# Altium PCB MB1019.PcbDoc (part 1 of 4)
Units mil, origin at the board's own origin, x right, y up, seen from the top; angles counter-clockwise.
Board outline 4655 x 6805 mil, 4 copper layers (TopLayer, VCC, GND, BottomLayer), stack 26.137 mil thick; 557 components, 425 nets, 1918 pads, 817 vias.
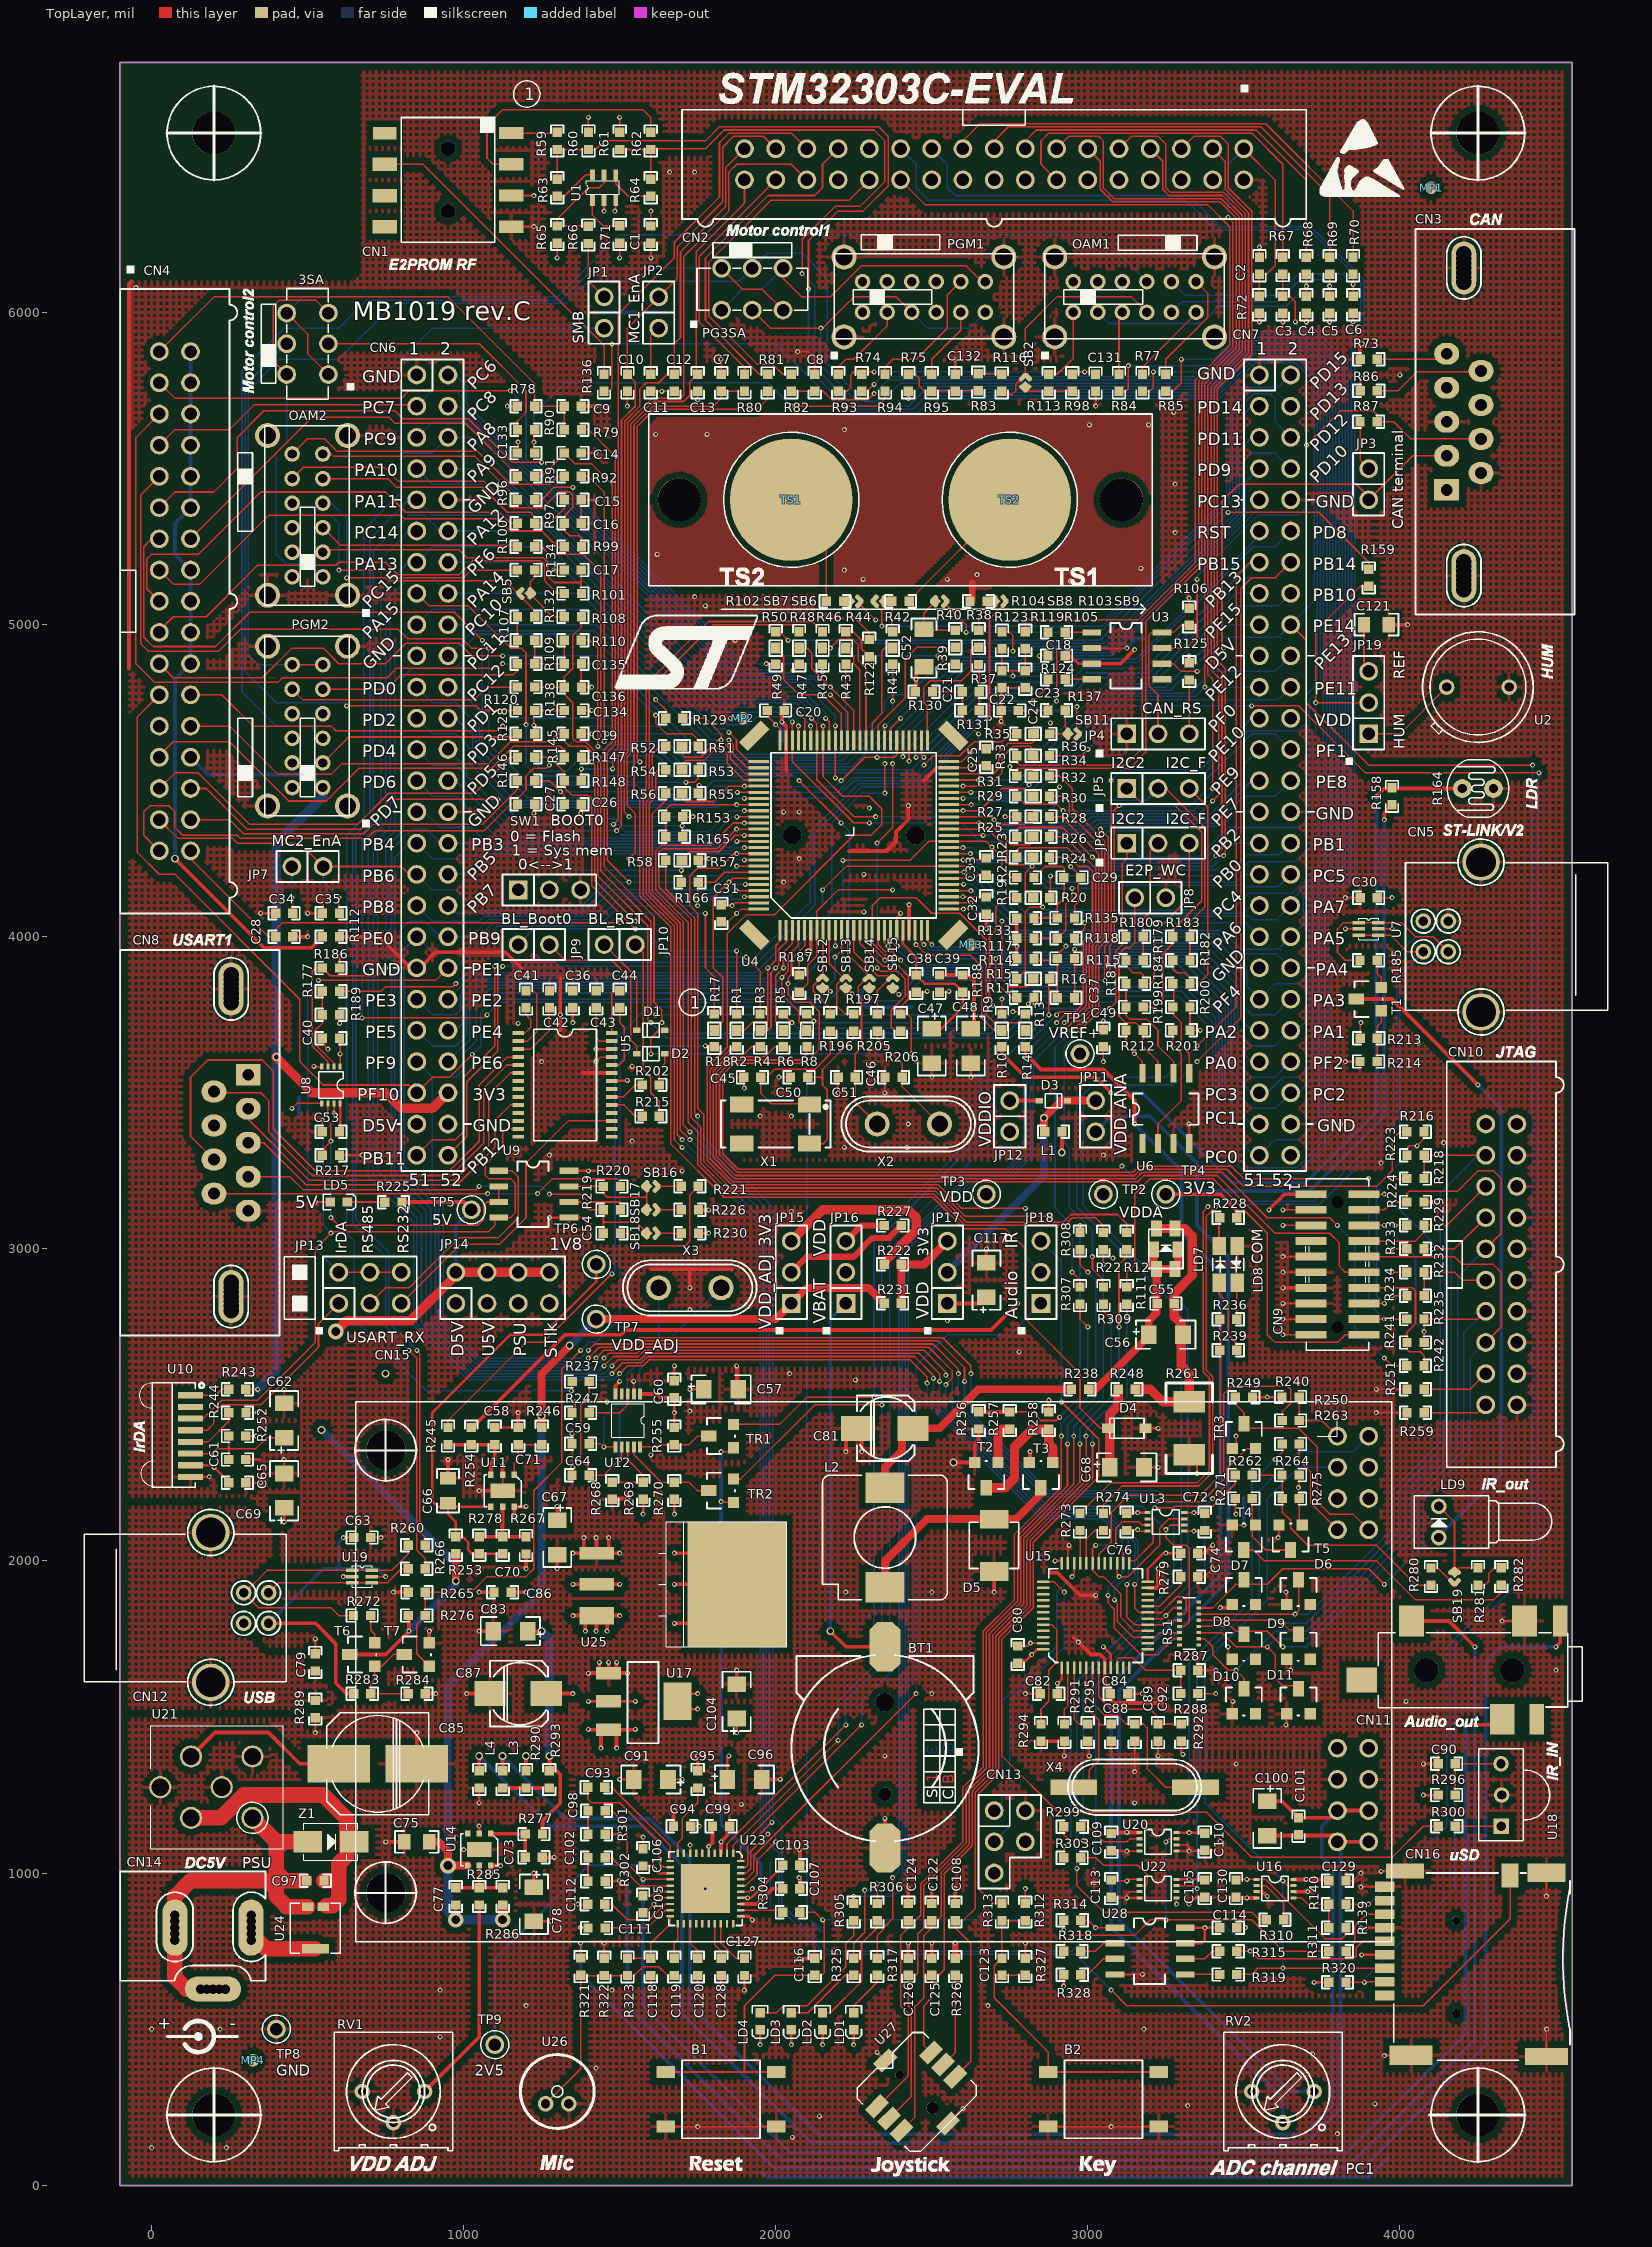
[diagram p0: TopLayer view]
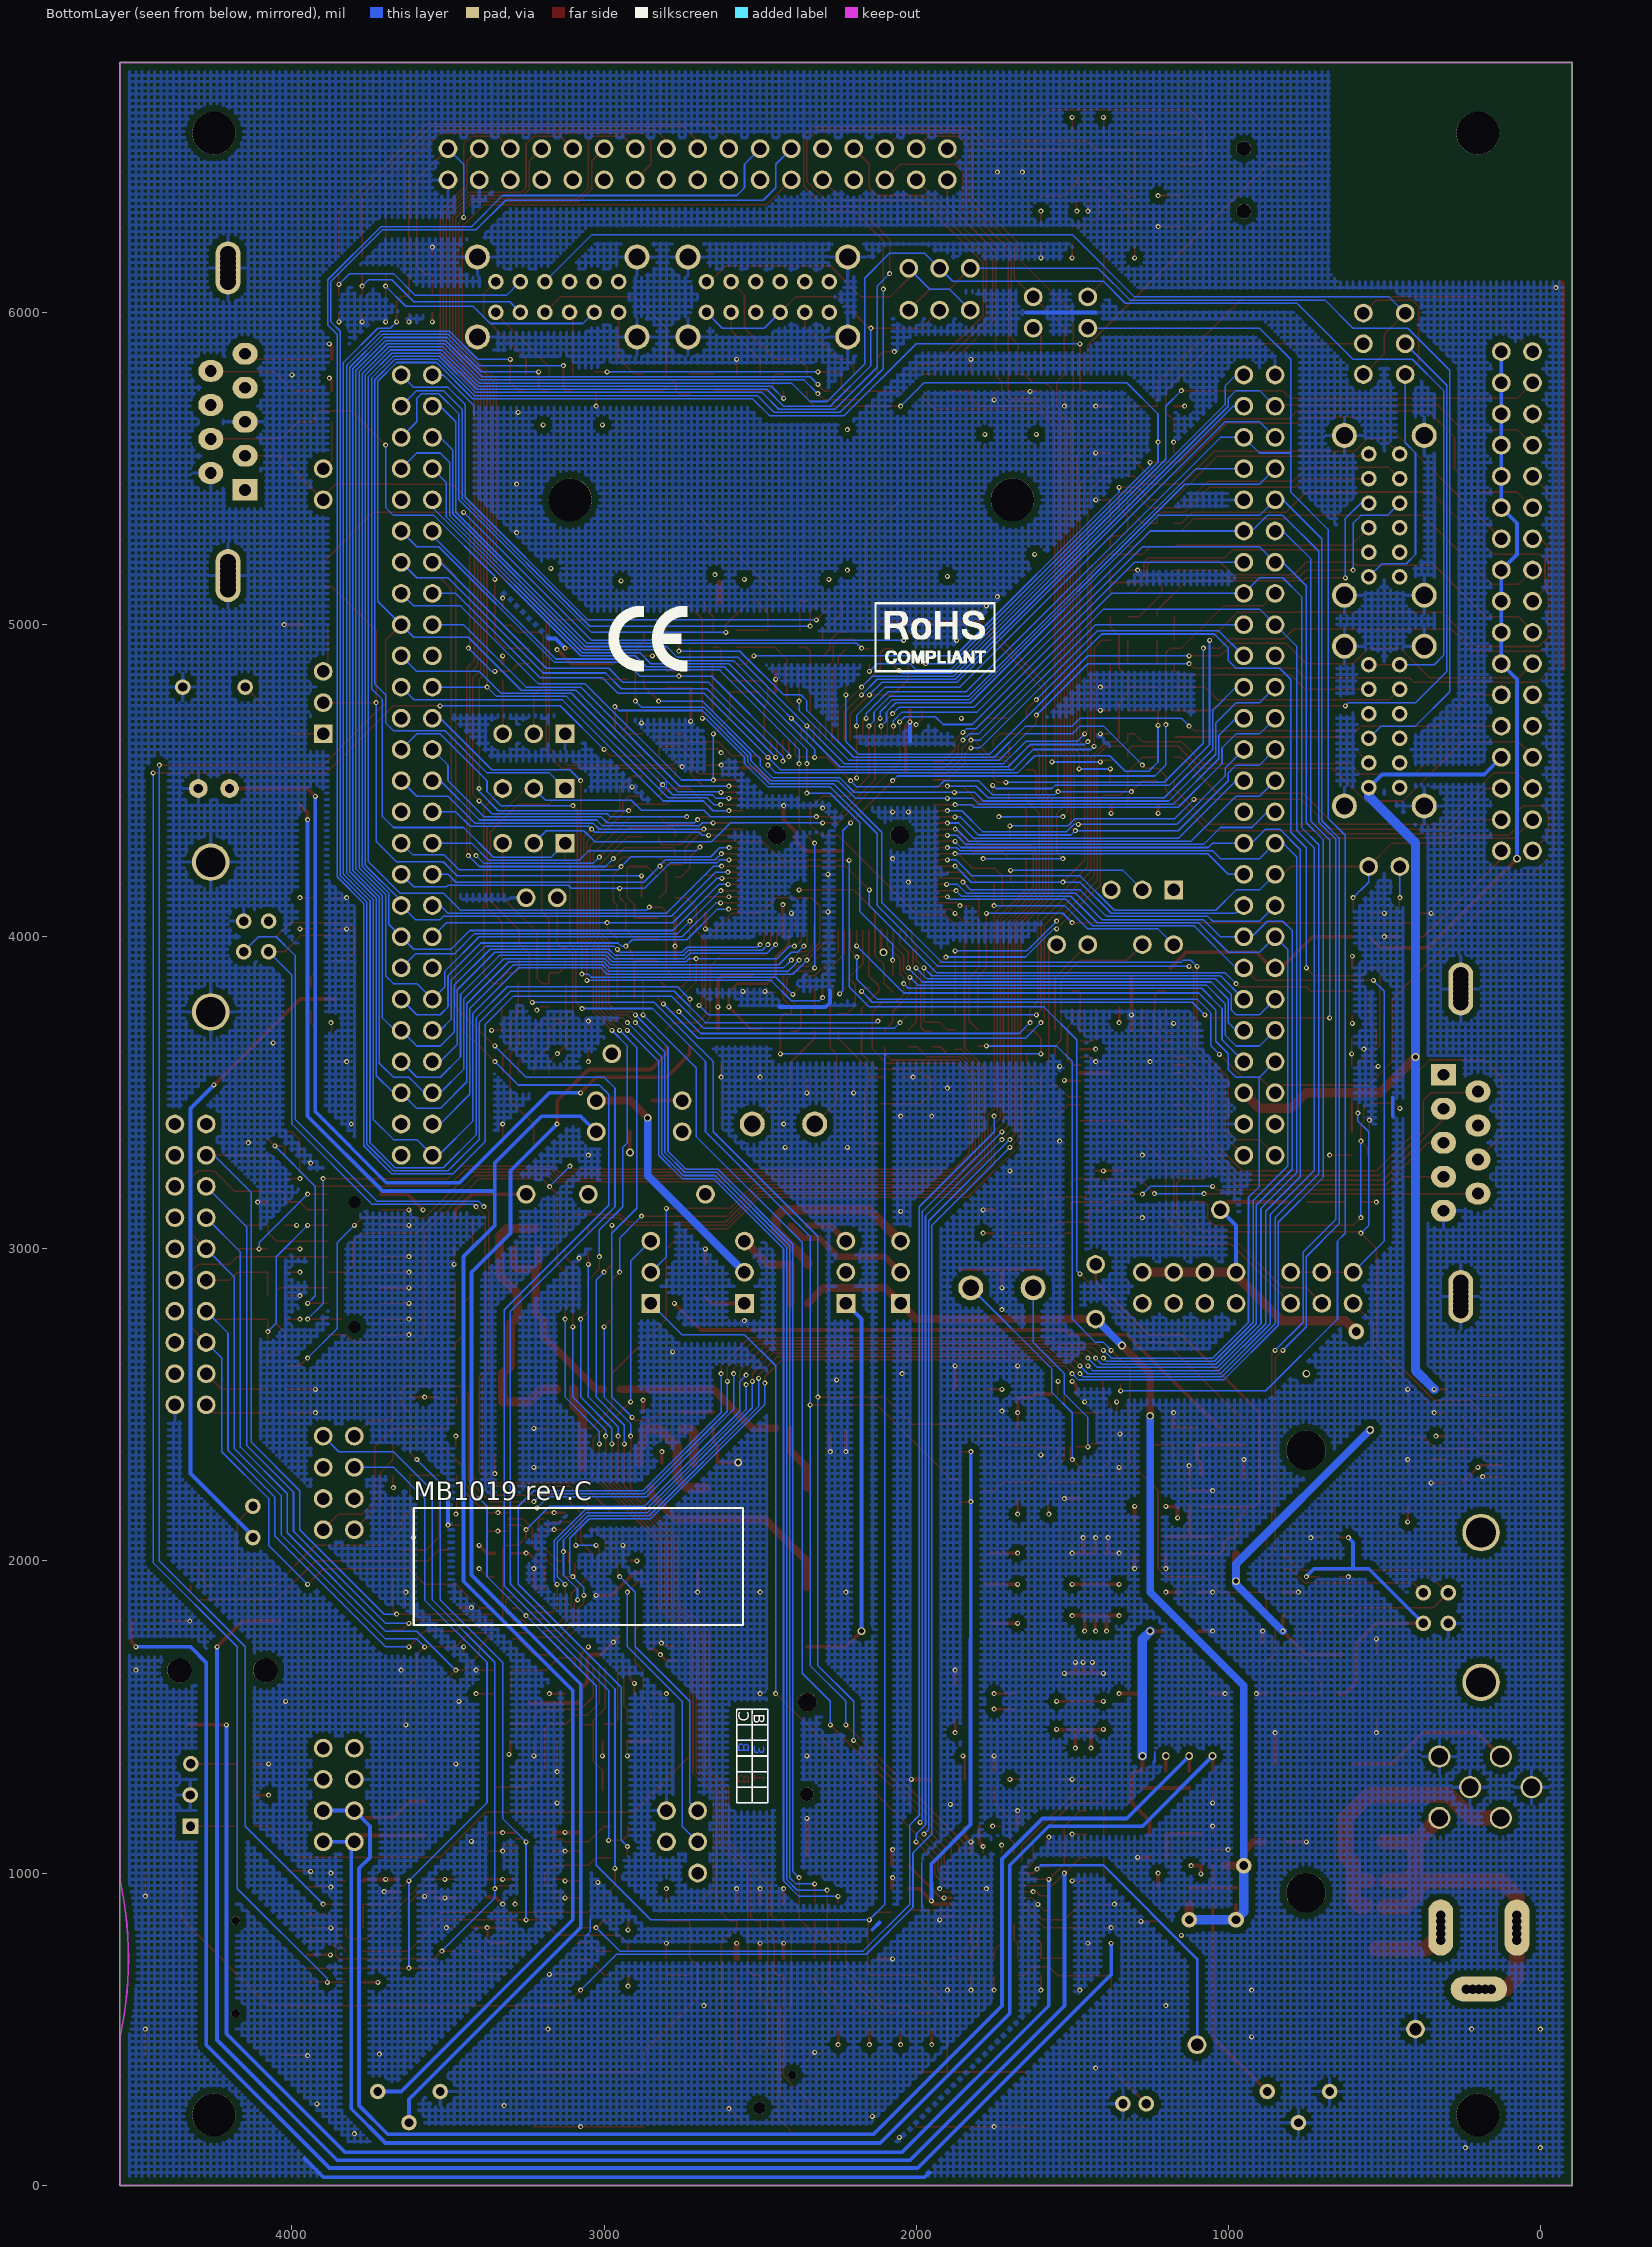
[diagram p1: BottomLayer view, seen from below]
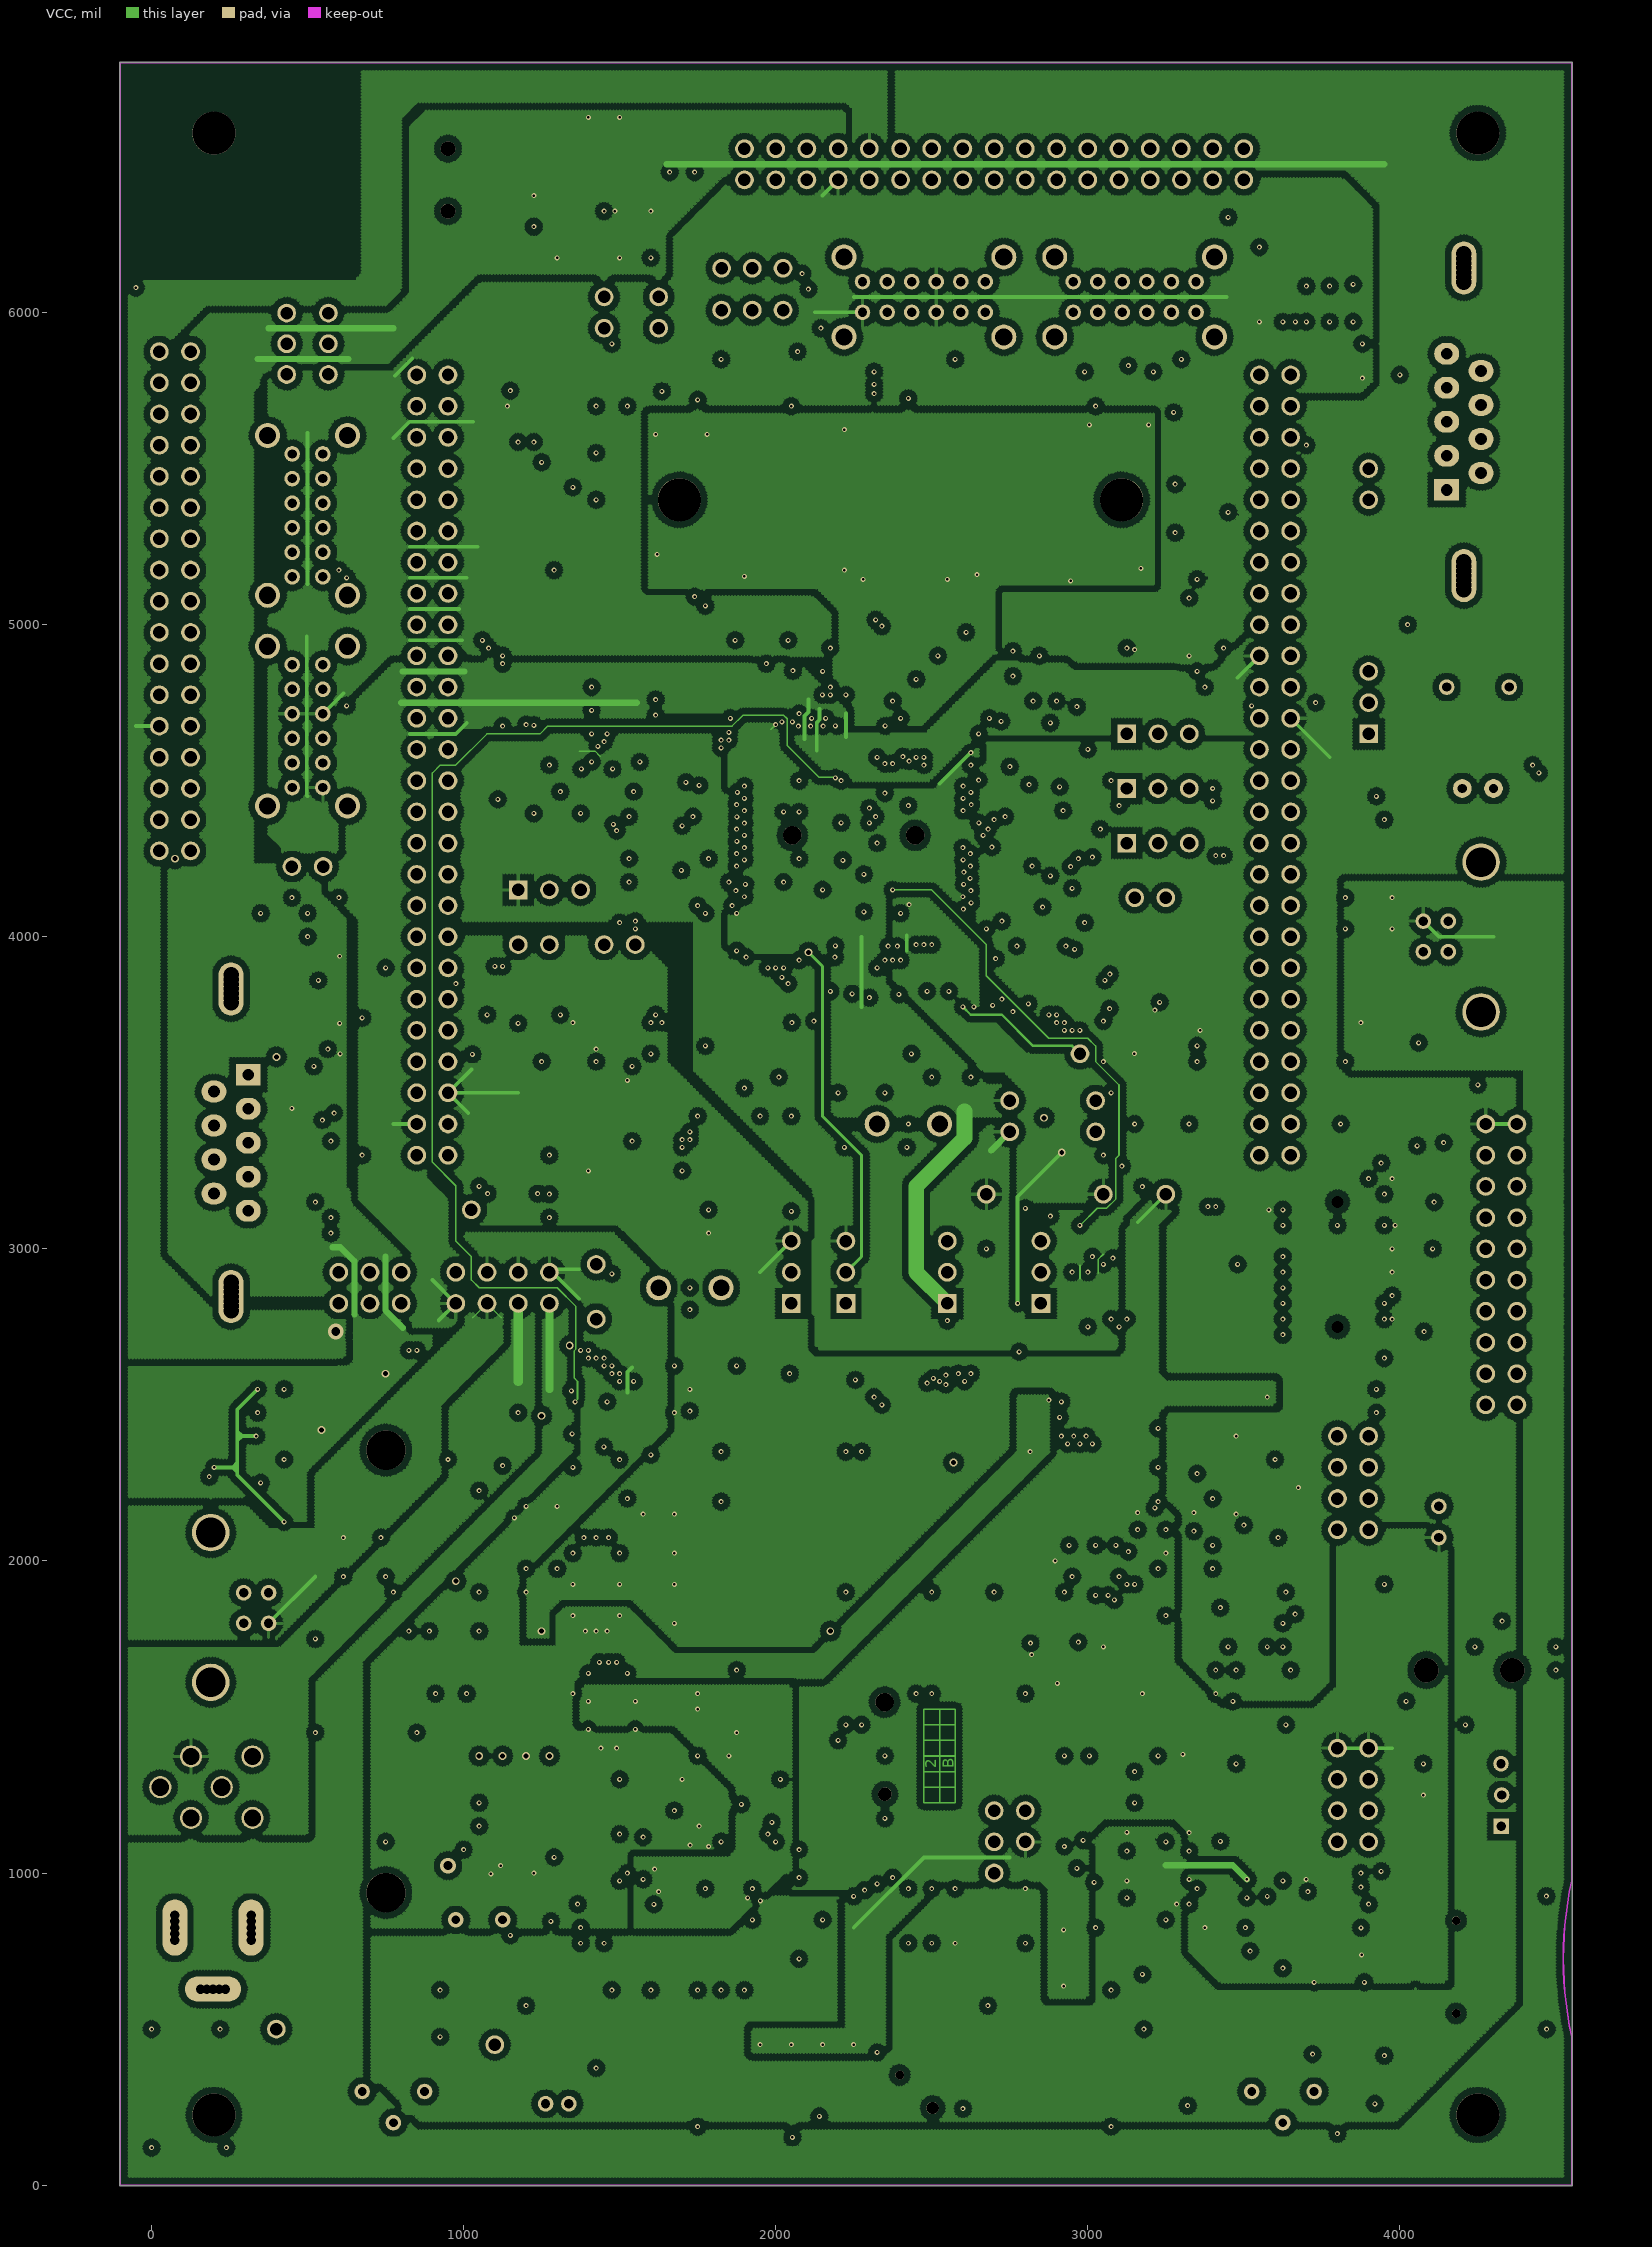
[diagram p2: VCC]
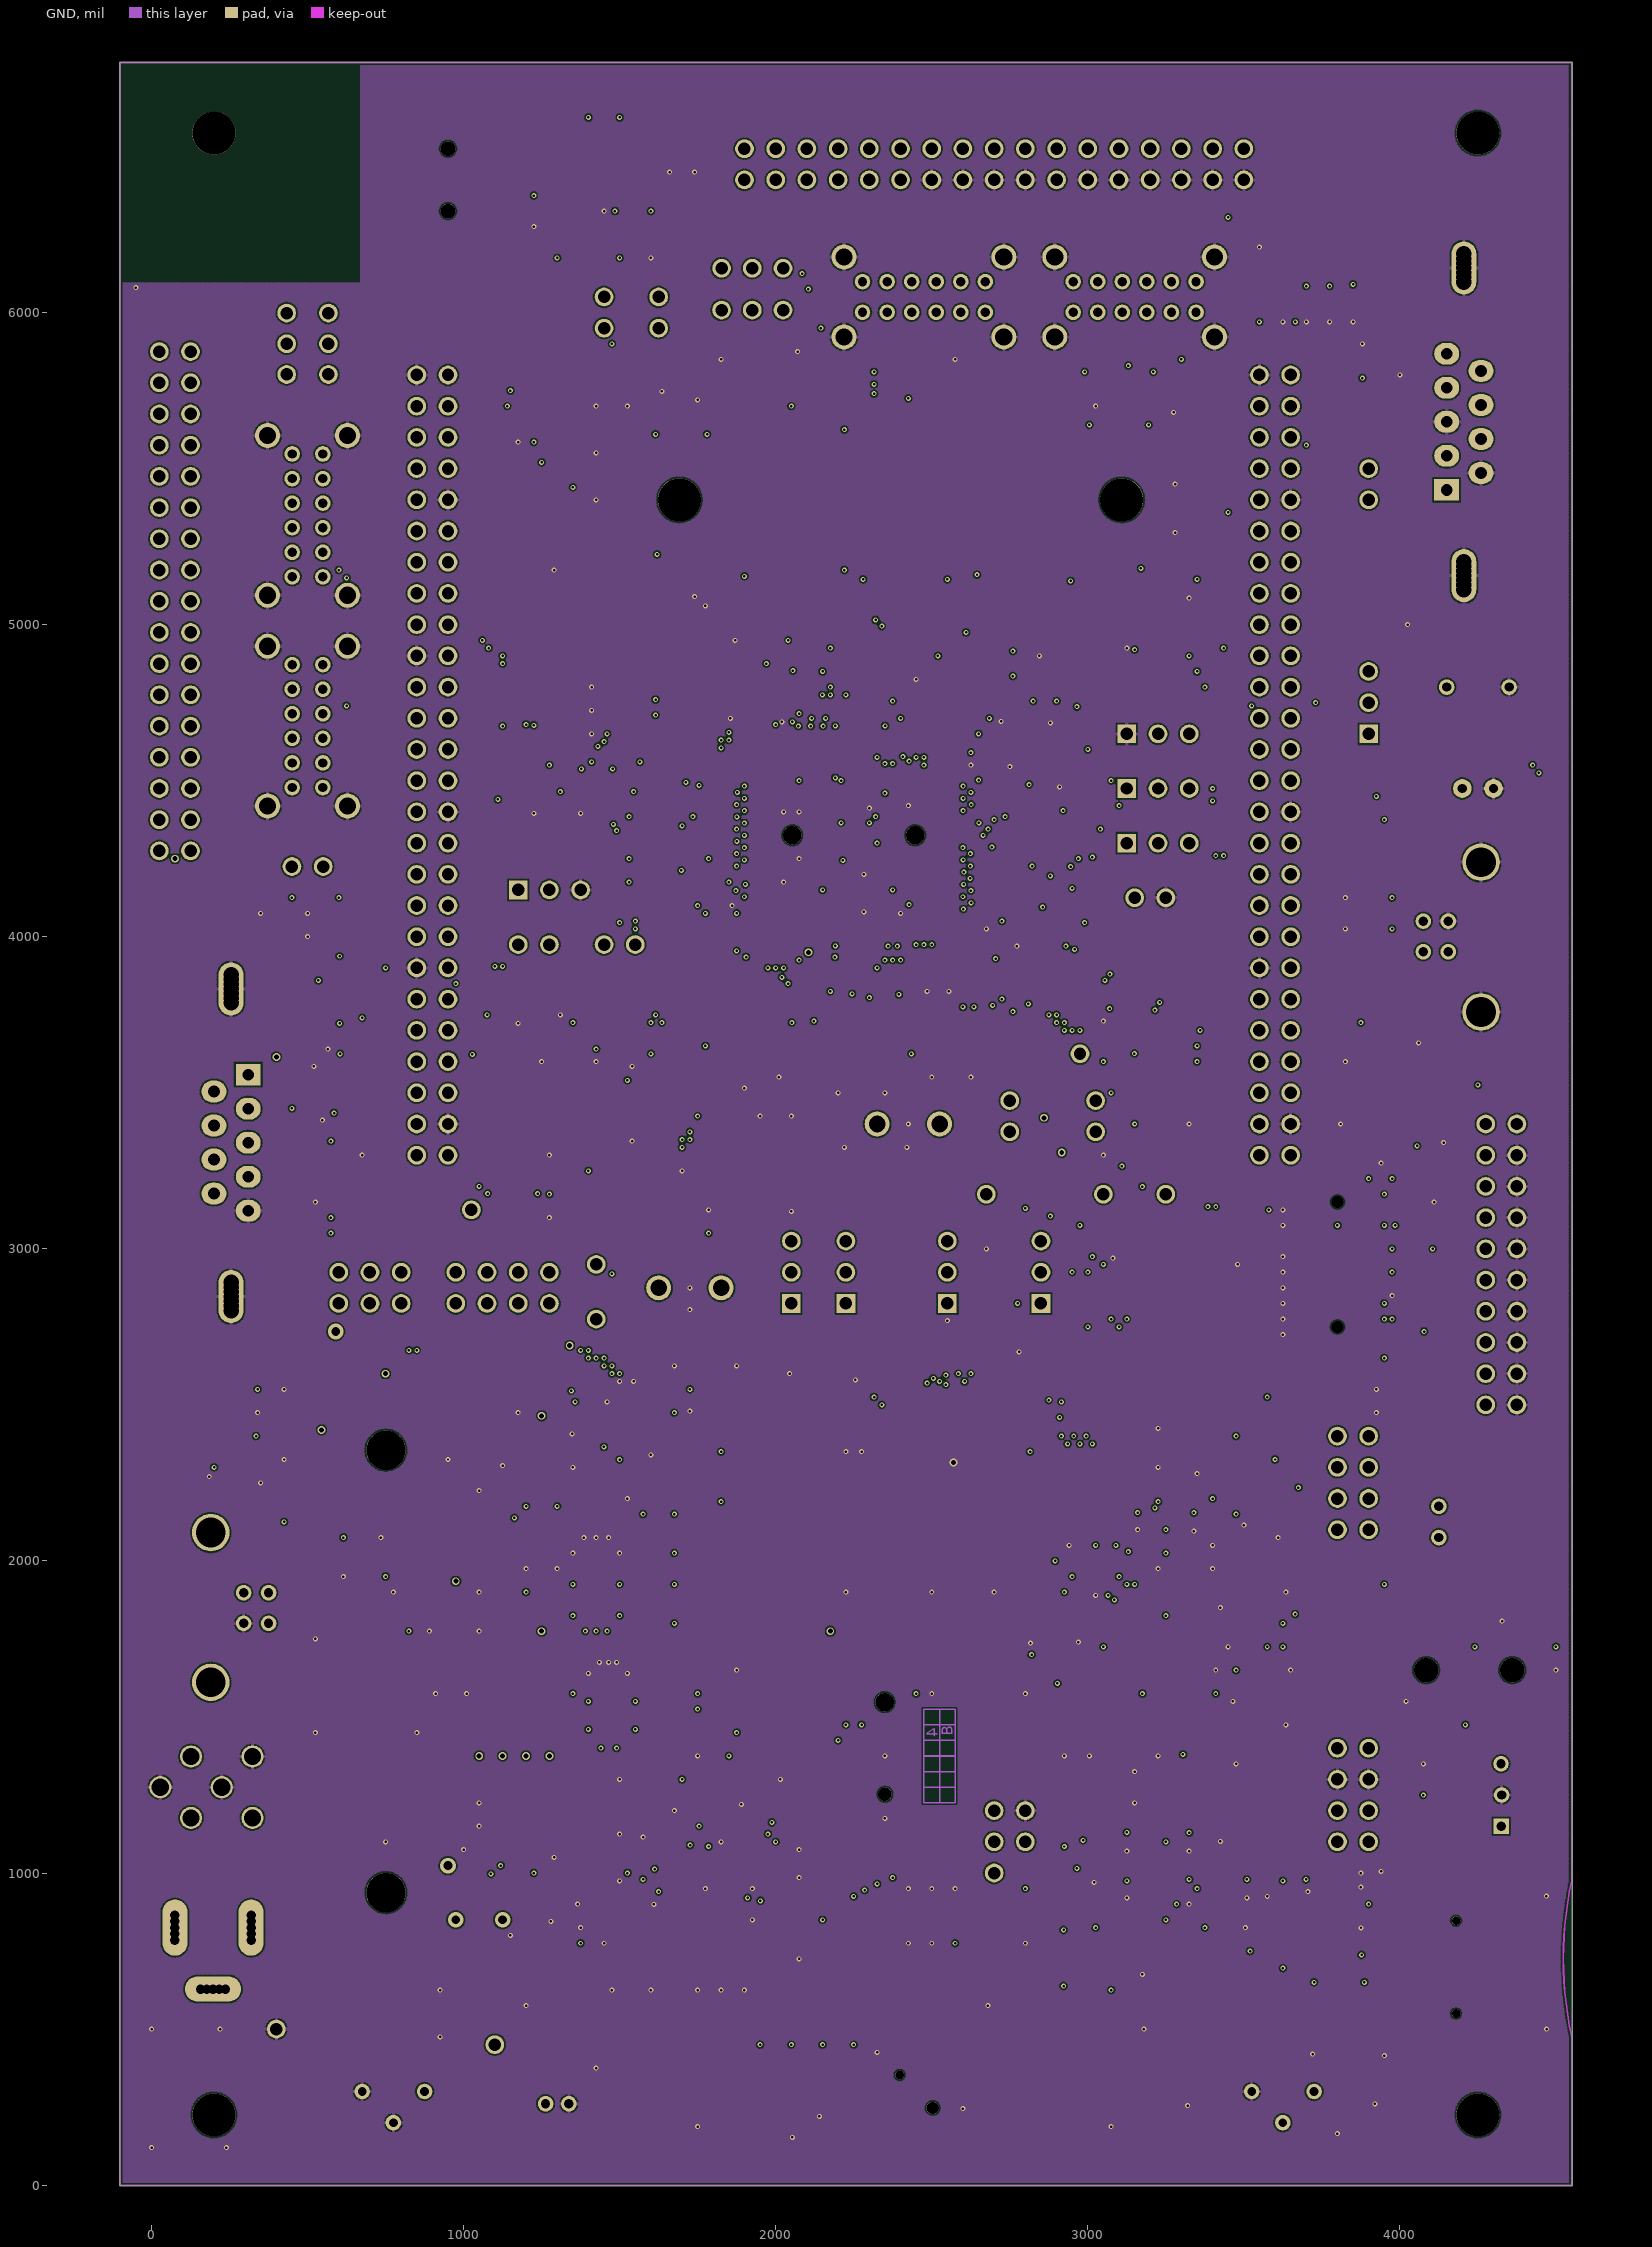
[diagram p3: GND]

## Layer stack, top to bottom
TopLayer: signal copper 1.4
Dielectric: core 4, FR-4, Dk 0.1
VCC: signal copper 1.4
Dielectric: prepreg 3.937, FR-4, Dk 4.8
GND: signal copper 1.4
Dielectric: core 12.6, FR-4, Dk 4.8
BottomLayer: signal copper 1.4

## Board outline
-102.5,-2.5 4552.5,-2.5 4552.5,6802.5 -102.5,6802.5

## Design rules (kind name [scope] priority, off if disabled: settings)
Clearance Clearance_2 [OnLayer('VCC') And ((InPoly)) vs OnLayer('VCC')] p1: gap=5
Clearance Clearance_1 [(InPoly)] p2 off: gap=20
Clearance [All] p3: gap=5
ComponentClearance [All] p1 off: gap=10 collisioncheckmode=3 verticalgap=10 showdistances=FALSE
FabricationTestPointUsage TestPointUsage [All] p1: valid=0 allowmultiple=FALSE
FabricationTestpoint Testpoint [All] p1: side=3 testpointundercomponent=TRUE minsize=40 maxsize=100 preferedsize=60 minholesize=20 maxholesize=40 preferedholesize=32 testpointgrid=1 allowsidetop=TRUE allowsidebottom=TRUE usegrid=TRUE gridtolerance=0.01
PolygonConnect [All] p1: connectstyle=Relief reliefconductorwidth=10 reliefentries=4 polygonreliefangle="90 Angle"
RoutingLayers [All] p1: top layer_v5=TRUE mid layer 1_v5=FALSE mid layer 2_v5=FALSE bottom layer_v5=TRUE
RoutingVias RoutingVias_1 [InNet('+1V2')] p1: holewidth=8 width=18 viastyle="Through Hole" minholewidth=8 minwidth=12 maxholewidth=28 maxwidth=50
RoutingVias RoutingVias_6 [InNet('+5V')] p2: holewidth=8 width=16 viastyle="Through Hole" minholewidth=8 minwidth=12 maxholewidth=28 maxwidth=50
RoutingVias RoutingVias_7 [InNet('E5V')] p3: holewidth=8 width=16 viastyle="Through Hole" minholewidth=8 minwidth=16 maxholewidth=28 maxwidth=50
RoutingVias RoutingVias_8 [InNet('EMU_3V3')] p4: holewidth=8 width=16 viastyle="Through Hole" minholewidth=8 minwidth=16 maxholewidth=28 maxwidth=50
RoutingVias RoutingVias_5 [InNet('+3V3')] p5: holewidth=8 width=16 viastyle="Through Hole" minholewidth=8 minwidth=12 maxholewidth=28 maxwidth=50
RoutingVias RoutingVias_2 [InNet('+1V8')] p6: holewidth=8 width=16 viastyle="Through Hole" minholewidth=8 minwidth=12 maxholewidth=28 maxwidth=50
RoutingVias RoutingVias_3 [InNet('+2V5')] p7: holewidth=8 width=16 viastyle="Through Hole" minholewidth=8 minwidth=8 maxholewidth=28 maxwidth=50
RoutingVias RoutingVias_4 [InNet('+2V8')] p8: holewidth=8 width=16 viastyle="Through Hole" minholewidth=8 minwidth=12 maxholewidth=28 maxwidth=50
RoutingVias RoutingVias_14 [InNet('VDD_MCU')] p9: holewidth=8 width=16 viastyle="Through Hole" minholewidth=8 minwidth=12 maxholewidth=28 maxwidth=50
RoutingVias RoutingVias_13 [InNet('VBUS_HS')] p10: holewidth=8 width=16 viastyle="Through Hole" minholewidth=8 minwidth=16 maxholewidth=28 maxwidth=50
RoutingVias RoutingVias_16 [InNet('VREF+')] p11: holewidth=8 width=16 viastyle="Through Hole" minholewidth=8 minwidth=12 maxholewidth=28 maxwidth=50
RoutingVias RoutingVias_15 [InNet('VDDA')] p12: holewidth=8 width=16 viastyle="Through Hole" minholewidth=8 minwidth=12 maxholewidth=28 maxwidth=50
RoutingVias RoutingVias_10 [InNet('GND')] p13: holewidth=8 width=16 viastyle="Through Hole" minholewidth=6 minwidth=12 maxholewidth=28 maxwidth=50
RoutingVias RoutingVias_9 [InNet('EMU_5V')] p14: holewidth=8 width=16 viastyle="Through Hole" minholewidth=8 minwidth=16 maxholewidth=28 maxwidth=50
RoutingVias RoutingVias_12 [InNet('VBUS_FS')] p15: holewidth=8 width=16 viastyle="Through Hole" minholewidth=8 minwidth=16 maxholewidth=28 maxwidth=50
RoutingVias RoutingVias_11 [InNet('U5V_ST_LINK')] p16: holewidth=8 width=16 viastyle="Through Hole" minholewidth=8 minwidth=16 maxholewidth=28 maxwidth=50
RoutingVias [All] p17: holewidth=8 width=16 viastyle="Through Hole" minholewidth=8 minwidth=16 maxholewidth=100 maxwidth=300
SilkscreenOverComponentPads [All] p1: minsilkscreentomaskgap=10
SolderMaskExpansion [All] p1: expansion=4
Width Width_6 [InNet('E5V')] p1: maxlimit=300 minlimit=8 preferedwidth=12
Width Width_10 [InNet('VREF+')] p2: maxlimit=300 minlimit=8 preferedwidth=8
Width Width_2 [InNet('+2V5')] p3: maxlimit=300 minlimit=5 preferedwidth=8
Width Width_3 [InNet('+2V8')] p4: maxlimit=300 minlimit=5 preferedwidth=8
Width Width_4 [InNet('D5V')] p5: maxlimit=300 minlimit=5 preferedwidth=12
Width Width_1 [InNet('+1V8')] p6: maxlimit=300 minlimit=5 preferedwidth=7.87
Width Width_5 [InNet('+3V3')] p7: maxlimit=300 minlimit=5 preferedwidth=12
Width Width_15 [InNet('VDD_MCU')] p8: maxlimit=300 minlimit=5 preferedwidth=8
Width Width_12 [InNet('GND')] p9: maxlimit=300 minlimit=5 preferedwidth=5
Width Width_13 [InNet('VDDA')] p10: maxlimit=300 minlimit=5 preferedwidth=12
Width Width_8 [InNet('+5V')] p11: maxlimit=300 minlimit=5 preferedwidth=12
Width Width_9 [InNet('EMU_3V3')] p12: maxlimit=300 minlimit=5 preferedwidth=12
Width Width_11 [InNet('EMU_5V')] p13: maxlimit=300 minlimit=5 preferedwidth=12
Width [All] p14: maxlimit=300 minlimit=3 preferedwidth=20
23 further rules are at their usual default settings.

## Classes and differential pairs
component class MB1019: JP5 JP6 MP1 MP2 MP3 MP4 R179 R180 R182 R183
component class TouchSensing: C24 C52 R102 R103 R104 R122 R137 SB6 SB7 SB8 SB9 SB11 TS1 TS2
component class RS232_RS485_IrDA: C36 C40 C41 C42 C43 C44 C53 C54 C61 C62 C65 C69 C107 C108 CN8 CN15 JP13 R177 R186 R189 R202 R215 R217 R219 R220 R221 R226 R230 R243 R244 R252 R291 R292 R319 R325 R326 SB16 SB17 SB18 U5 U8 U9 U10 U28
component class I2CPeripherals: C1 C49 CN1 JP8 R59 R60 R61 R62 R63 R64 R65 R66 R71 R181 R184 R199 R200 R201 R212 U1 U6
component class CAN&Humidity_Sensor&HB_LED&IR: C18 C55 C56 C68 C81 C90 CN3 D4 D5 JP3 JP4 L2 LD8 R73 R86 R87 R105 R106 R124 R125 R159 R238 R248 R256 R257 R258 R261 R262 R264 R271 R275 R280 R281 R282 R296 R300 SB19 T2 T3 T4 T5 U2 U3 U18
component class LCD_MicroSD_Flash: C100 C101 C109 C110 C113 C114 C115 CN15 CN16 L3 L4 R240 R249 R250 R263 R290 R293 R299 R303 R310 R311 R314 R315 R318 R319 R320 R328 TR3 U20 U22 U28
component class Peripherals: B2 C63 C79 C108 C117 C122 C123 C124 C125 C126 CN12 LD8 R158 R164 R260 R265 R266 R272 R276 R283 R284 R289 R305 R306 R307 R308 R309 R312 R313 R317 R325 R326 R327 RV2 T6 T7 U19 U27
component class MotorCtrl: 3SA C2 C3 C4 C5 C6 C7 C8 C9 C10 C11 C12 C13 C14 C15 C16 C17 C19 C21 C22 C23 C26 C27 C28 C29 C33 C34 C35 C37 C131 C132 C133 C134 C135 C136 CN2 CN4 JP2 JP7 OAM1 OAM2 PG3SA PGM1 PGM2 R67 R68 R69 R70 R72 R74 R75 R77 R78 R79 R80 R81 R82 R83 R84 R85 R90 R91 R92 R93 R94 R95 R96 R97 R98 R99 R100 R101 R107 R108 R109 R110 R119 R120 R123 R128 R138 R145 R146 R147 R148 R153 R165 SB1 SB2 SB3 SB4 SB5 SB10
net class A[0..20]: A0 A1 A2 A3 A4 A5 A6 A7 A8 A9 A10 A11 A12 A13 A14 A15 A16 A17 A18 A19 A20 A[0..20]0 A[0..20]1 A[0..20]2 A[0..20]3 A[0..20]4 A[0..20]5 A[0..20]6 A[0..20]7 A[0..20]8 A[0..20]9 A[0..20]10 A[0..20]11 A[0..20]12 A[0..20]13 A[0..20]14 A[0..20]15 A[0..20]16 A[0..20]17 A[0..20]18 A[0..20]19 A[0..20]20
component class ST_LINK: C27 C34 C35 C118 C119 C133 C134 C135 C138 C139 CN5 CN21 LD8 R84 R90 R94 R107 R109 R128 R138 R146 R165 R200 R304 R317 T4 U27 X5
component class SRAM&OneNAND: C28 C30 C103 C111 C112 R7 R10 R31 R32 R33 R38 R103 R105 R119 U3 U20
net class ULPI_D[0..7]: ULPI_D0 ULPI_D1 ULPI_D2 ULPI_D3 ULPI_D4 ULPI_D5 ULPI_D6 ULPI_D7 ULPI_D[0..7]0 ULPI_D[0..7]1 ULPI_D[0..7]2 ULPI_D[0..7]3 ULPI_D[0..7]4 ULPI_D[0..7]5 ULPI_D[0..7]6 ULPI_D[0..7]7
net class A[0..17]: A0 A1 A2 A3 A4 A5 A6 A7 A8 A9 A10 A11 A12 A13 A14 A15 A16 A17 A[0..17]0 A[0..17]1 A[0..17]2 A[0..17]3 A[0..17]4 A[0..17]5 A[0..17]6 A[0..17]7 A[0..17]8 A[0..17]9 A[0..17]10 A[0..17]11 A[0..17]12 A[0..17]13 A[0..17]14 A[0..17]15 A[0..17]16 A[0..17]17
net class D[0..15]: D0 D1 D2 D3 D4 D5 D6 D7 D8 D9 D10 D11 D12 D13 D14 D15 D[0..15]0 D[0..15]1 D[0..15]2 D[0..15]3 D[0..15]4 D[0..15]5 D[0..15]6 D[0..15]7 D[0..15]8 D[0..15]9 D[0..15]10 D[0..15]11 D[0..15]12 D[0..15]13 D[0..15]14 D[0..15]15
net class PI[0..11]: PI0 PI1 PI2 PI3 PI4 PI5 PI6 PI7 PI8 PI9 PI10 PI11 PI[0..11]0 PI[0..11]1 PI[0..11]2 PI[0..11]3 PI[0..11]4 PI[0..11]5 PI[0..11]6 PI[0..11]7 PI[0..11]8 PI[0..11]9 PI[0..11]10 PI[0..11]11
net class PH[0..15]: PH0 PH1 PH2 PH3 PH4 PH5 PH6 PH7 PH8 PH9 PH10 PH11 PH12 PH13 PH14 PH15 PH[0..15]0 PH[0..15]1 PH[0..15]2 PH[0..15]3 PH[0..15]4 PH[0..15]5 PH[0..15]6 PH[0..15]7 PH[0..15]8 PH[0..15]9 PH[0..15]10 PH[0..15]11 PH[0..15]12 PH[0..15]13 PH[0..15]14 PH[0..15]15
net class PG[0..15]: PG0 PG2 PG3 PG3SA PG4 PG5 PG6 PG7 PG8 PG9 PG10 PG11 PG12 PG13 PG14 PG15 PG[0..15]0 PG[0..15]1 PG[0..15]2 PG[0..15]3 PG[0..15]4 PG[0..15]5 PG[0..15]6 PG[0..15]7 PG[0..15]8 PG[0..15]9 PG[0..15]10 PG[0..15]11 PG[0..15]12 PG[0..15]13 PG[0..15]14 PG[0..15]15
net class PF[0..15]: PF0 PF1 PF2 PF3 PF4 PF5 PF6 PF7 PF8 PF9 PF10 PF11 PF12 PF13 PF14 PF15 PF[0..15]0 PF[0..15]1 PF[0..15]2 PF[0..15]3 PF[0..15]4 PF[0..15]5 PF[0..15]6 PF[0..15]7 PF[0..15]8 PF[0..15]9 PF[0..15]10 PF[0..15]11 PF[0..15]12 PF[0..15]13 PF[0..15]14 PF[0..15]15
net class DCMI_D[0..7]: DCMI_D0 DCMI_D1 DCMI_D2 DCMI_D3 DCMI_D4 DCMI_D5 DCMI_D6 DCMI_D7 DCMI_D[0..7]0 DCMI_D[0..7]1 DCMI_D[0..7]2 DCMI_D[0..7]3 DCMI_D[0..7]4 DCMI_D[0..7]5 DCMI_D[0..7]6 DCMI_D[0..7]7
component class MB786: R61 R166 R218 R256
component class PSRAM&OneNAND: C28 C30 C103 C111 C112 R6 R7 R10 R31 R32 R33 R38 R103 R105 R119 U3 U20
component class USB_OTG_HS: C1 C29 C31 C49 C68 C90 C110 C113 C115 C127 C128 CN15 L2 L3 LD8 R1 R3 R4 R34 R57 R58 U16 U18 U26 X1
component class Cameraconnector: C38 C66 C70 CN15 JP26 R233 R238 R258 U8
component class MCU: B1 C2 C9 C37 C56 C126 D1 D2 JP3 JP6 JP7 JP8 JP10 JP11 JP12 JP17 R57 R71 R79 R196 R205 R240 R290 R320 SW1 SW2 TP2 X2 X3
component class IOPeripherals: B2 B3 B4 C7 C32 C40 C44 C46 C47 C53 C65 C98 C107 C108 CN5 CN15 JP2 LD8 R12 R16 R18 R19 R21 R22 R35 R36 R39 R57 R58 R61 R86 R124 R166 R187 R206 R218 R256 R269 R271 R275 R281 R282 R298 R316 R321 R324 RV1 SB12 SB17 U2 U23 U26
component class Power: BT1 C12 C15 C17 C22 C24 C28 C30 C31 C39 C45 C52 C58 C91 C94 C116 C120 CN20 JP5 JP14 JP22 L2 LD8 R6 R7 R10 R13 R31 R32 R33 R38 R65 R82 R103 R105 R119 T4 T5 TP1 TP3 TP4 TP6 TP13 U2 U9 U14 U15 U25 U27 U28 Z1
component class Ethernet: C8 C13 C23 C38 C63 C66 C70 C81 C117 C122 C124 CN3 JP15 JP19 JP26 R1 R4 R23 R29 R34 R36 R39 R57 R58 R66 R67 R68 R69 R106 R125 R146 R148 R153 R224 R233 R234 R238 R248 R257 R258 R261 R268 R300 R303 TP7 U8 U10 X4
component class USB_OTG_FS: C33 CN6 LD8 R11 R24 R25 R27 R30 R58 R247 U18 U19
component class CAN: C34 C79 CN3 JP9 JP20 JP21 JP23 R2 R5 R26 R28 R57 R60 R63 R159 R229 R232 R235 R242 U20 U26
component class SmartCard: C3 C18 C33 C83 C85 C87 C108 C125 CN2 R3 R39 R80 R106 R110 R247 R311 R318 R319 TP1 TP2 U1
component class USART&IrDA: C10 C29 C31 C49 C68 C110 C113 C115 C128 CN10 JP4 R148 R241 U6 U17
component class Audio: C1 C20 C25 C41 C43 C48 C54 C55 C59 C62 C69 C84 C86 C90 C102 C104 C127 CN4 R81 R223 R251 R259 R263 R293 R328 U21 U22
component class MotorControl: C42 C57 C60 C92 C93 C95 C96 C99 C105 C106 C107 C109 C121 CN1 JP1 JP22 R10 R14 R19 R20 R57 R91 R123 R147
component class IO_Expandor: C21 C29 R58 R78 R249 R250 R296 R302 R314 U16 U18
component class ExtensionConnector: CN15 CN16 R73 R87 SB16 SB18
component class JTAG&Trace: C134 CN8 CN14 JP18 R35 R38 R39 R40 R57 R58 R59 R62 R199 R237 R280 R301
component class LCD: CN9 CN13
component class MicroSDCard: CN1 R58 R70 R72 R181
component class MB784: R64 R184 R201 R212
net class PA[0..15]: CAMERA_CLK CAMERA_RST NetC62_2 NetCN13_2 NetCN13_4 NetCN13_8 NetR238_2 PA0 PA1 PA2 PA3 PA4 PA6 PA7 PA[0..15]0 PA[0..15]1 PA[0..15]2 PA[0..15]3 PA[0..15]4 PA[0..15]5 PA[0..15]6 PA[0..15]7 PA[0..15]8 PA[0..15]9 PA[0..15]10 PA[0..15]11 PA[0..15]12 PA[0..15]13 PA[0..15]14 PA[0..15]15 PI5 PI7
net class PB[0..15]: NetCN13_6 NetR17_2 NetRS7_12 PB0 PB1 PB2 PB5 PB6 PB7 PB9 PB10 PB11 PB12 PB13 PB14 PB15 PB[0..15]0 PB[0..15]1 PB[0..15]2 PB[0..15]3 PB[0..15]4 PB[0..15]5 PB[0..15]6 PB[0..15]7 PB[0..15]8 PB[0..15]9 PB[0..15]10 PB[0..15]11 PB[0..15]12 PB[0..15]13 PB[0..15]14 PB[0..15]15
net class PC[0..15]: NetJP16_1 PA6 PC0 PC1 PC2 PC3 PC4 PC5 PC6 PC7 PC8 PC13 PC14 PC15 PC[0..15]0 PC[0..15]1 PC[0..15]2 PC[0..15]3 PC[0..15]4 PC[0..15]5 PC[0..15]6 PC[0..15]7 PC[0..15]8 PC[0..15]9 PC[0..15]10 PC[0..15]11 PC[0..15]12 PC[0..15]13 PC[0..15]14 PC[0..15]15 PH10 PH14
net class PD[0..15]: NetR90_2 NetSB14_1 NetU13_7 PD1 PD2 PD3 PD4 PD5 PD6 PD7 PD8 PD9 PD11 PD14 PD15 PD[0..15]0 PD[0..15]1 PD[0..15]2 PD[0..15]3 PD[0..15]4 PD[0..15]5 PD[0..15]6 PD[0..15]7 PD[0..15]8 PD[0..15]9 PD[0..15]10 PD[0..15]11 PD[0..15]12 PD[0..15]13 PD[0..15]14 PD[0..15]15 PH11
net class PE[0..15]: PE0 PE1 PE2 PE3 PE4 PE5 PE6 PE7 PE8 PE9 PE10 PE11 PE12 PE13 PE14 PE15 PE[0..15]0 PE[0..15]1 PE[0..15]2 PE[0..15]3 PE[0..15]4 PE[0..15]5 PE[0..15]6 PE[0..15]7 PE[0..15]8 PE[0..15]9 PE[0..15]10 PE[0..15]11 PE[0..15]12 PE[0..15]13 PE[0..15]14 PE[0..15]15

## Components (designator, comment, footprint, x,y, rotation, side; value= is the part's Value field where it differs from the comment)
3SA "MS22D16" MS22D16 500,5900 r90 top
B1 "TD-0341 [RESET/Black]" PB10 1825,275 r0 top
B2 "USER (Blue)" PB10 3050,275 r0 top
BT1 "CR1220 holder" LI1220_1 2350,1400 r90 top
C1 "100nF" 0603C 1600,6250 r270 top
C2 "1nF" 0603C 3550,6150 r90 top
C3 "[N/A]" 0603C 3625,6025 r90 top
C4 "[N/A]" 0603C 3700,6025 r270 top
C5 "[N/A]" 0603C 3775,6025 r270 top
C6 "[N/A]" 0603C 3850,6025 r270 top
C7 "[N/A]" 0603C 1825,5775 r90 top
C8 "[N/A]" 0603C 2125,5775 r90 top
C9 "1nF" 0603C 1350,5700 r0 top
C10 "[N/A]" 0603C 1525,5775 r270 top
C11 "10nF" 0603C 1600,5775 r270 top
C12 "[N/A]" 0603C 1675,5775 r270 top
C13 "[N/A]" 0603C 1750,5775 r270 top
C14 "[N/A]" 0603C 1350,5550 r180 top
C15 "[N/A]" 0603C 1350,5400 r0 top
C16 "[N/A]" 0603C 1350,5325 r0 top
C17 "[N/A]" 0603C 1350,5175 r180 top
C18 "100nF" 0603C 2900,4900 r180 top
C19 "[N/A]" 0603C 1350,4650 r0 top
C20 "100nF" 0603C 2000,4725 r180 top
C21 "[N/A]" 0603C 2625,4785 r0 top
C22 "[N/A]" 0603C 2725,4825 r270 top
C23 "[N/A]" 0603C 2800,4825 r270 top
C24 "220nF" 0603C 2750,4725 r180 top
C25 "100nF" 0603C 2675,4575 r90 top
C26 "[N/A]" 0603C 1350,4425 r0 top
C27 "[N/A]" 0603C 1200,4425 r0 top
C28 "[N/A]" 0603C 425,4000 r0 top
C29 "[N/A]" 0603C 2950,4190 r0 top
C30 "100nF" 0603C 3900,4125 r0 top
C31 "100nF" 0603C 1825,4075 r90 top
C32 "100nF" 0603C 2675,4100 r90 top
C33 "[N/A]" 0603C 2675,4225 r270 top
C34 "10nF" 0603C 425,4075 r180 top
C35 "[N/A]" 0603C 575,4075 r180 top
C36 "100nF" 0603C 1350,3800 r90 top
C37 "[N/A]" 0603C 2930,3805 r0 top
C38 "100nF" 0603C 2450,3850 r270 top
C39 "10nF" 0603C 2525,3850 r270 top
C40 "100nF" 0603C 575,3675 r180 top
C41 "100nF" 0603C 1200,3800 r270 top
C42 "100nF" 0603C 1275,3800 r270 top
C43 "100nF" 0603C 1425,3800 r270 top
C44 "100nF" 0603C 1500,3800 r270 top
C45 "10pF" 0603C 1925,3550 r0 top
C46 "20pF" 0603C 2377.5,3550 r0 top
C47 "1uF" TAN-A 2500,3650 r90 top
C48 "1uF" TAN-A 2625,3650 r90 top
C49 "100nF" 0603C 3050,3675 r90 top
C50 "10pF" 0603C 2075,3550 r0 top
C51 "20pF" 0603C 2227.5,3550 r0 top
C52 "47nF(COG)GRM31M5C1H473JA01L" 1206C 2475,4925 r270 top
C53 "100nF" 0603C 575,3375 r180 top
C54 "100nF" 0603C 1475,3050 r0 top
C55 "100nF" 0603C 3250,2825 r0 top
C56 "10uF" TAN-A 3250,2725 r180 top
C57 "1uF" TAN-A 1825,2550 r180 top
C58 "100nF" 0603C 1100,2400 r270 top
C59 "[N/A]" 0603C 1375,2375 r0 top
C60 "100nF" 0603C 1675,2550 r270 top
C61 "100nF" 0603C 275,2325 r180 top
C62 "4.7uF" TAN-A 425,2450 r270 top
C63 "100nF" 0603C 675,2075 r180 top
C64 "[N/A]" 0603C 1375,2275 r0 top
C65 "100nF" 0603C 275,2250 r180 top
C66 "10uF" 0805C 950,2225 r270 top
C67 "4.7uF" TAN-A 1300,2075 r90 top
C68 "1uF" TAN-A 3125,2300 r180 top
C69 "4.7uF" TAN-A 425,2225 r270 top
C70 "[N/A]" 0603C 1125,2050 r90 top
C71 "100nF[N/A]" 0603C 1175,2400 r270 top
C72 "100nF" 0603C 3375,2125 r90 top
C73 "100nF" 0603C 1225,1050 r180 top
C74 "100nF" 0603C 3325,2025 r0 top
C75 "10uF" 0805C 850,1100 r0 top
C76 "100nF" 0603C 3125,2125 r270 top
C77 "[N/A]" 0603C 975,925 r90 top
C78 "4.7uF" TAN-A 1225,900 r90 top
C79 "4.7nF" 0603C 525,1675 r90 top
C80 "100nF" 0603C 2775,1700 r90 top
C81 "47uF" C200M 2350,2425 r0 top
C82 "100nF" 0603C 2875,1575 r0 top
C83 "10uF" TAN-A 1150,1775 r0 top
C84 "100nF" 0603C 3100,1575 r180 top
C85 "220uF" C310M 725,1350 r180 top
C86 "100nF" 0603C 1125,1900 r0 top
C87 "47uF" C200M 1175,1575 r0 top
C88 "20pF" 0603C 3075,1450 r270 top
C89 "20pF" 0603C 3150,1450 r270 top
C90 "4.7uF" 0603C 4150,1350 r0 top
C91 "10uF" TAN-A 1600,1300 r0 top
C92 "100nF" 0603C 3225,1450 r270 top
C93 "1uF" 0603C 1425,1275 r180 top
C94 "100nF" 0603C 1700,1150 r0 top
C95 "1uF" 0603C 1750,1300 r270 top
C96 "1uF" TAN-A 1900,1300 r180 top
C97 "100nF" 0603C 525,975 r0 top
C98 "0.022uF" 0603C 1426,1199 r180 top
C99 "100nF" 0603C 1825,1150 r180 top
C100 "10uF" TAN-A 3575,1175 r90 top
C101 "100nF" 0603C 3675,1150 r90 top
C102 "0.022uF" 0603C 1426,1049 r180 top
C103 "100nF" 0603C 2050,1025 r180 top
C104 "10uF" TAN-A 1875,1550 r270 top
C105 "100nF" 0603C 1575,900 r90 top
C106 "100nF" 0603C 1575,1050 r270 top
C107 "100nF" 0603C 2050,950 r180 top
C108 "100nF" 0603C 2575,875 r90 top
C109 "100nF" 0603C 3075,1099 r270 top
C110 "100nF" 0603C 3375,1100 r270 top
C111 "1uF" 0603C 1426,824 r180 top
C112 "1uF" 0603C 1425,900 r180 top
C113 "100nF" 0603C 3075,950 r270 top
C114 "100nF" 0603C 3450,825 r180 top
C115 "100nF" 0603C 3375,950 r270 top
C116 "100nF" 0603C 2125,700 r90 top
C117 "4.7uF" TAN-A 2675,2900 r270 top
C118 "100nF" 0603C 1600,699 r90 top
C119 "1uF" 0603C 1675,699 r90 top
C120 "1uF" 0603C 1750,699 r90 top
C121 "08051A181FAT2A 180pF[1%]" 0805C 3925,5000 r0 top
C122 "100nF" 0603C 2500,875 r90 top
C123 "100nF" 0603C 2725,700 r270 top
C124 "100nF" 0603C 2425,875 r90 top
C125 "100nF" 0603C 2500,700 r90 top
C126 "100nF" 0603C 2425,700 r90 top
C127 "150pF(COG)" 0603C 1900,699 r270 top
C128 "150pF(COG)" 0603C 1825,699 r270 top
C129 "100nF" 0603C 3800,975 r0 top
C130 "100nF" 0603C 3475,950 r270 top
C131 "120pF" 0603R#1 3025,5775 r90 top
C132 "120pF" 0603R#1 2575,5775 r270 top
C133 "120pF" 0603R#1 1200,5550 r0 top
C134 "120pF" 0603R#1 1350,4725 r180 top
C135 "120pF" 0603R#1 1350,4875 r180 top
C136 "120pF" 0603R#1 1350,4800 r180 top
CN1 "SSM-104-L-DH" SSM-104-L-DH 950,6425 r0 top
CN2 "MC_connector" IDC34S 3500,6525 r270 top locked
CN3 "DB9-male CAN connector" DB9/M 4150,5650 r270 top
CN4 "MC_connector" IDC34S 25,5875 r0 top
CN5 "USB-typeB connector" USB-B 4075,4050 r90 top
CN6 "2213S-52G" 2*26P 850,5800 r0 top locked
CN7 "2213S-52G" 2*26P 3550,5800 r0 top locked
CN8 "DB9-male USART1" DB9/M 310,3340 r90 top
CN9 "FTSH-110-01-L-DV" FTSH-110-01-L-DV 3800,2950 r270 top
CN10 "JTAG" IDC20S 4275,3400 r0 top locked
CN11 "PJ3028B-3" PJ3028B 4360,1650 r180 top
CN12 "USB-typeB connector" USB-B 375,1800 r270 top
CN13 "JTAG" 2*3P#1 2700,1200 r0 top
CN14 "DC-10B" DC10B 75,825 r0 top
CN15 "2.4\" LCD connector" MB895CS 3800,2400 r0 top locked
CN16 "PJS008-2000 (SMS064FF or SMS128FF)" MSD(PJS008) 4180,550 r90 top
D1 "BAT60J" SOD-323 1600,3700 r0 top
D2 "BAT60J" SOD-323 1600,3625 r0 top
D3 "BAT60J" SOD-323 2890,3475 r180 top
D4 "MMSZ5227BT1" SOD-123 3125,2425 r0 top
D5 "STPS340" SMB 2700,2050 r270 top
D6 "Z5V1" SOT-23 3675,1900 r270 top
D7 "[N/A]" SOT-23 3500,1900 r270 top
D8 "Z5V1" SOT-23 3500,1725 r270 top
D9 "Z5V1" SOT-23 3675,1725 r270 top
D10 "Z5V1" SOT-23 3500,1550 r270 top
D11 "Z5V1" SOT-23 3675,1550 r270 top
JP1 "" SIP2 1450,5950 r90 top
JP2 "" SIP2 1625,6050 r270 top
JP3 "" SIP2 3900,5500 r270 top
JP4 "" SIP3 3125,4650 r0 top
JP5 "" SIP3 3125,4475 r0 top
JP6 "" SIP3 3125,4300 r0 top
JP7 "" SIP2 550,4225 r180 top
JP8 "" SIP2 3150,4125 r0 top
JP9 "" SIP2 1275,3975 r180 top
JP10 "" SIP2 1450,3975 r0 top
JP11 "" SIP2 3025,3375 r90 top
JP12 "" SIP2 2750,3475 r270 top
JP13 "Header 3X2" 2*3P#2 600,2825 r90 top
JP14 "Header 4X2" 2*4P 975,2825 r90 top
JP15 "" SIP3 2050,2825 r90 top
JP16 "" SIP3 2225,2825 r90 top
JP17 "" SIP3 2550,2825 r90 top
JP18 "" SIP3 2850,2825 r90 top
JP19 "" SIP3 3900,4650 r90 top
L1 "BEAD" 0603L 2890,3375 r180 top
L2 "330uH" SLF10145 2350,2075 r270 top
L3 "BEAD" 0603L 1125,1300 r270 top
L4 "BEAD" 0603L 1050,1300 r270 top
LD1 "Green" 0603D 2250,525 r270 top
LD2 "Orange" 0603D 2150,525 r270 top
LD3 "Red" 0603D 2050,525 r270 top
LD4 "Blue" 0603D 1950,525 r270 top
LD5 "red" 0603D 600,3150 r0 top
LD7 "Amber" PLCC4 3250,3000 r0 top
LD8 "HSMF-A201-A00J1" LED2-28*32 3450,2950 r180 top
LD9 "SFH409-2" D0.1L 4125,2125 r90 top
MP1 "" markpoint_1.0 4100,6400 r0 top
MP2 "" markpoint_1.0 1895,4700 r0 top
MP3 "" markpoint_1.0 2625,3975 r0 top
MP4 "" markpoint_1.0 325,400 r0 top
OAM1 "SS42D02" SS42D02 3150,6050 r0 top
OAM2 "SS42D02" SS42D02 500,5350 r90 top
PG3SA "MS22D16" MS22D16 1925,6075 r0 top
PGM1 "SS42D02" SS42D02 2475,6050 r0 top
PGM2 "SS42D02" SS42D02 500,4675 r90 top
R1 "[N/A]" 0603R#1 1875,3725 r90 top
R2 "0" 0603R#1 1875,3675 r270 top
R3 "[N/A]" 0603R#1 1950,3725 r90 top
R4 "0" 0603R#1 1950,3675 r270 top
R5 "[N/A]" 0603R#1 2024,3725 r90 top
R6 "0" 0603R#1 2024,3675 r270 top
R7 "[N/A]" 0603R#1 2100,3725 r90 top
R8 "0" 0603R#1 2100,3675 r270 top
R9 "[N/A]" 0603R#1 2725,3725 r270 top
R10 "0" 0603R#1 2725,3675 r90 top
R11 "0" 0603R#1 2800,3805 r180 top
R12 "0" 0603R#1 3125,3025 r90 top
R13 "[N/A]" 0603R#1 2800,3725 r90 top
R14 "0" 0603R#1 2800,3675 r270 top
R15 "[N/A]" 0603R#1 2800,3865 r0 top
R16 "0" 0603R#1 2850,3865 r180 top
R17 "[N/A]" 0603R#1 1803,3725 r270 top
R18 "0" 0603R#1 1803,3675 r90 top
R19 "[N/A]" 0603R#1 2800,4125 r0 top
R20 "0" 0603R#1 2850,4125 r180 top
R21 "[N/A]" 0603R#1 2800,4190 r180 top
R22 "0" 0603R#1 3050,3025 r90 top
R23 "[N/A]" 0603R#1 2800,4255 r180 top
R24 "0" 0603R#1 2850,4255 r0 top
R25 "[N/A]" 0603R#1 2800,4320 r180 top
R26 "0" 0603R#1 2850,4320 r0 top
R27 "[N/A]" 0603R#1 2800,4385 r180 top
R28 "0" 0603R#1 2850,4385 r0 top
R29 "[N/A]" 0603R#1 2800,4450 r180 top
R30 "0" 0603R#1 2850,4450 r0 top
R31 "[N/A]" 0603R#1 2800,4515 r180 top
R32 "0" 0603R#1 2850,4515 r0 top
R33 "[N/A]" 0603R#1 2800,4580 r180 top
R34 "0" 0603R#1 2850,4580 r0 top
R35 "[N/A]" 0603R#1 2800.5,4650 r0 top
R36 "0" 0603R#1 2850,4650 r180 top
R37 "[N/A]" 0603R#1 2650,4900 r90 top
R38 "0" 0603R#1 2650,4955 r270 top
R39 "[N/A]" 0603R#1 2575,4900 r270 top
R40 "0" 0603R#1 2575,4955 r90 top
R41 "[N/A]" 0603R#1 2375,4900 r270 top
R42 "0" 0603R#1 2375,4950 r90 top
R43 "[N/A]" 0603R#1 2225,4900 r270 top
R44 "0" 0603R#1 2225,4950 r90 top
R45 "[N/A]" 0603R#1 2150,4900 r270 top
R46 "0" 0603R#1 2150,4950 r90 top
R47 "[N/A]" 0603R#1 2075,4900 r270 top
R48 "0" 0603R#1 2075,4950 r90 top
R49 "[N/A]" 0603R#1 2000,4900 r270 top
R50 "0" 0603R#1 2000,4950 r90 top
R51 "[N/A]" 0603R#1 1725,4610 r0 top
R52 "0" 0603R#1 1675,4610 r180 top
R53 "[N/A]" 0603R#1 1725,4535 r0 top
R54 "0" 0603R#1 1675,4535 r180 top
R55 "[N/A]" 0603R#1 1725,4460 r0 top
R56 "0" 0603R#1 1675,4460 r180 top
R57 "[N/A]" 0603R#1 1725,4245 r0 top
R58 "0" 0603R#1 1675,4245 r180 top
R59 "0" 0603R#1 1300,6550 r270 top
R60 "4K7" 0603R#1 1400,6550 r270 top
R61 "4K7" 0603R#1 1500,6550 r270 top
R62 "0" 0603R#1 1600,6550 r270 top
R63 "0" 0603R#1 1300,6400 r90 top
R64 "0" 0603R#1 1600,6400 r90 top
R65 "4K7" 0603R#1 1300,6250 r90 top
R66 "0" 0603R#1 1399,6249 r90 top
R67 "0" 0603R#1 3625,6150 r270 top
R68 "0" 0603R#1 3700,6150 r90 top
R69 "0" 0603R#1 3775,6150 r90 top
R70 "0" 0603R#1 3850,6150 r90 top
R71 "7K5[5%]" 0603R#1 1500,6250 r270 top
R72 "3.3K" 0603R#1 3550,6025 r90 top
R73 "0" 0603R#1 3900,5850 r180 top
R74 "0" 0603R#1 2275,5775 r270 top
R75 "0" 0603R#1 2425,5775 r270 top
R77 "0" 0603R#1 3175,5775 r270 top
R78 "3.3K" 0603R#1 1200,5700 r0 top
R79 "0" 0603R#1 1350,5625 r180 top
R80 "0" 0603R#1 1900,5775 r270 top
R81 "0" 0603R#1 1975,5775 r90 top
R82 "0" 0603R#1 2050,5775 r90 top
R83 "4.99K[1%]" 0603R#1 2649,5777 r90 top
R84 "0" 0603R#1 3100,5775 r270 top
R85 "0" 0603R#1 3250,5775 r90 top
R86 "[N/A]" 0603R#1 3900,5750 r180 top
R87 "120" 0603R#1 3900,5650 r0 top
R90 "4.99K[1%]" 0603R#1 1200,5625 r180 top
R91 "0" 0603R#1 1200,5475 r0 top
R92 "0" 0603R#1 1350,5475 r0 top
R93 "13K[1%]" 0603R#1 2200,5775 r270 top
R94 "13K[1%]" 0603R#1 2350,5775 r270 top
R95 "13K[1%]" 0603R#1 2500,5775 r270 top
R96 "0" 0603R#1 1200,5400 r0 top
R97 "0" 0603R#1 1200,5325 r180 top
R98 "4.99K[1%]" 0603R#1 2950,5775 r270 top
R99 "0" 0603R#1 1350,5250 r180 top
R100 "0" 0603R#1 1200,5250 r0 top
R101 "0" 0603R#1 1350,5100 r180 top
R102 "10K" 0603R#1 2190,5075 r0 top
R103 "2K2" 0603R#1 2650,5075 r0 top
R104 "10K" 0603R#1 2400,5075 r180 top
R105 "0" 0603R#1 2900,4975 r0 top
R106 "10K" 0603R#1 3325,5025 r270 top
R107 "4.99K[1%]" 0603R#1 1200,4950 r180 top
R108 "4.99K[1%]" 0603R#1 1350,5025 r180 top
R109 "13K[1%]" 0603R#1 1200,4875 r0 top
R110 "0" 0603R#1 1350,4950 r0 top
R111 "0" 0603R#1 3125,2850 r270 top
R112 "0" 0603R#1 575,4000 r0 top
R113 "0" 0603R#1 2875,5775 r270 top
R114 "[N/A]" 0603R#1 2800,3930 r180 top
R115 "[N/A]" 0603R#1 2930,3930 r0 top
R116 "0" 0603R#1 2725,5775 r90 top
R117 "[N/A]" 0603R#1 2800,3995 r180 top
R118 "[N/A]" 0603R#1 2930,3995 r0 top
R119 "0" 0603R#1 2800,4950 r270 top
R120 "13K[1%]" 0603R#1 1200,4800 r0 top
R122 "0" 0603R#1 2300,4925 r90 top
R123 "[N/A]" 0603R#1 2725,4950 r270 top
R124 "0" 0603R#1 2900,4825 r180 top
R125 "0" 0603R#1 3325,4850 r270 top
R128 "13K[1%]" 0603R#1 1200,4650 r0 top
R129 "0" 0603R#1 1675,4700 r180 top
R130 "[N/A]" 0603R#1 2475,4785 r180 top
R131 "[N/A]" 0603R#1 2625,4725 r0 top
R132 "0" 0603R#1 1200,5025 r180 top
R133 "[N/A]" 0603R#1 2800,4060 r180 top
R134 "0" 0603R#1 1200,5175 r0 top
R135 "[N/A]" 0603R#1 2930,4060 r0 top
R136 "0" 0603R#2 1450,5775 r270 top
R137 "0" 0603R#1 2900,4725 r0 top
R138 "4.99K[1%]" 0603R#1 1200,4725 r180 top
R139 "10K" 0603R#2 3800,825 r180 top
R140 "0" 0603R#2 3800,900 r180 top
R145 "N/A" 0603R#1 1200,4575 r180 top
R146 "[N/A]" 0603R#1 1200,4500 r0 top
R147 "N/A" 0603R#1 1350,4575 r180 top
R148 "0" 0603R#1 1350,4500 r0 top
R153 "0" 0603R#1 1675,4385 r180 top
R158 "8.2K" 0603R#1 3975,4450 r90 top
R159 "82.5K[1%]" 0603R#1 3900,5150 r270 top
R164 "VT9ON1" PVT901 4250,4475 r270 top
R165 "[N/A]" 0603R#1 1675,4320 r180 top
R166 "10K" 0603R#1 1725,4175 r0 top
R177 "0" 0603R#1 575,3825 r180 top
R179 "N/A" 0603R#1 3150,3925 r180 top
R180 "N/A" 0603R#1 3150,4000 r180 top
R181 "0" 0603R#1 3150,3850 r180 top
R182 "N/A" 0603R#1 3300,3925 r180 top
R183 "N/A" 0603R#1 3300,4000 r180 top
R184 "0" 0603R#1 3300,3850 r180 top
R185 "1.5K" 0603R#1 3900,3925 r0 top
R186 "100K" 0603R#1 575,3900 r180 top
R187 "820" 0603R#1 2075,3850 r270 top
R188 "0" 0603R#1 2600,3850 r90 top
R189 "100K" 0603R#1 575,3750 r180 top
R196 "0" 0603R#1 2175,3725 r270 top
R197 "0" 0603R#1 2250,3725 r270 top
R199 "1.8K" 0603R#1 3150,3775 r180 top
R200 "1.8K" 0603R#1 3300,3775 r180 top
R201 "0" 0603R#1 3300,3700 r0 top
R202 "510" 0603R#1 1600,3525 r0 top
R205 "0" 0603R#1 2325,3725 r90 top
R206 "820" 0603R#1 2400,3725 r270 top
R212 "10K" 0603R#1 3150,3700 r180 top
R213 "10K" 0603R#1 3900,3675 r180 top
R214 "36K" 0603R#1 3900,3600 r0 top
R215 "0" 0603R#1 1600,3425 r0 top
R216 "0" 0603R#1 4050,3375 r0 top
R217 "10K" 0603R#1 575,3300 r0 top
R218 "[N/A]" 0603R#1 4050,3225 r0 top
R219 "0" 0603R#1 1475,3125 r180 top
R220 "0" 0603R#1 1475,3200 r180 top
R221 "120" 0603R#1 1725,3200 r0 top
R222 "0" 0603R#1 2375,2950 r0 top
R223 "[N/A]" 0603R#1 4050,3300 r180 top
R224 "[N/A]" 0603R#1 4050,3150 r0 top
R225 "1K" 0603R#1 775,3150 r180 top
R226 "22K" 0603R#1 1725,3125 r180 top
R227 "0" 0603R#1 2375,3075 r180 top
R228 "0" 0603R#1 3450,3100 r180 top
R229 "[N/A]" 0603R#1 4050,3075 r0 top
R230 "22K" 0603R#1 1725,3050 r180 top
R231 "[N/A]" 0603R#1 2375,2825 r0 top
R232 "[N/A]" 0603R#1 4050,2925 r0 top
R233 "[N/A]" 0603R#1 4050,3000 r0 top
R234 "10K" 0603R#1 4050,2850 r180 top
R235 "[N/A]" 0603R#1 4050,2775 r0 top
R236 "100" 0603R#1 3450,2775 r180 top
R237 "0" 0603R#1 1375,2575 r180 top
R238 "0" 0603R#1 2975,2550 r180 top
R239 "100" 0603R#1 3450,2675 r180 top
R240 "10K" 0603R#1 3650,2525 r0 top
R241 "[N/A]" 0603R#1 4050,2700 r180 top
R242 "0" 0603R#1 4050,2625 r0 top
R243 "5" 0603R#1 275,2550 r0 top
R244 "0" 0603R#1 275,2475 r180 top
R245 "[N/A]" 0603R#1 950,2400 r90 top
R246 "1K" 0603R#1 1250,2400 r270 top
R247 "0" 0603R#1 1375,2475 r0 top
R248 "10K" 0603R#1 3125,2550 r180 top
R249 "4K7" 0603R#1 3500,2525 r180 top
R250 "0" 0603R#1 3650,2450 r180 top
R251 "10K" 0603R#1 4050,2550 r180 top
R252 "47" 0603R#1 275,2400 r0 top
R253 "[N/A]" 0603R#1 975,2050 r270 top
R254 "[N/A]" 0603R#1 1025,2400 r90 top
R255 "10K" 0603R#1 1675,2400 r90 top
R256 "1K" 0603R#1 2650,2450 r270 top
R257 "0" 0603R#1 2750,2450 r90 top
R258 "180" 0603R#1 2875,2450 r90 top
R259 "10K" 0603R#1 4050,2475 r180 top
R260 "0" 0603R#1 850,2050 r0 top
R261 "10[0.5W]" 2010R 3325,2425 r270 top
R262 "0" 0603R#1 3500,2275 r0 top
R263 "270" 0603R#1 3650,2375 r180 top
R264 "10K" 0603R#1 3650,2275 r0 top
R265 "[N/A]" 0603R#1 850,1900 r180 top
R266 "0" 0603R#1 850,1975 r0 top
R267 "31.6K[1%]" 0603R#1 1200,2050 r90 top
R268 "0" 0603R#1 1476,2225 r270 top
R269 "10K" 0603R#1 1576,2225 r270 top
R270 "10K" 0603R#1 1675,2225 r270 top
R271 "2K2" 0603R#1 3500,2200 r0 top
R272 "1.5K" 0603R#1 675,1825 r0 top
R273 "0" 0603R#1 2975,2125 r270 top
R274 "0" 0603R#1 3050,2125 r270 top
R275 "1K" 0603R#1 3650,2200 r180 top
R276 "47K" 0603R#1 850,1825 r0 top
R277 "4K7" 0603R#1 1225,1125 r180 top
R278 "15K[1%]" 0603R#1 1050,2050 r270 top
R279 "100K" 0603R#1 3325,1950 r180 top
R280 "100" 0603R#1 4100,1950 r90 top
R281 "0" 0603R#1 4250,1950 r270 top
R282 "22" 0603R#1 4325,1950 r270 top
R283 "10K" 0603R#1 675,1575 r180 top
R284 "36K" 0603R#1 850,1575 r180 top
R285 "31.6K[1%]" 0603R#1 1050,925 r90 top
R286 "59K[1%]" 0603R#1 1125,925 r270 top
R287 "4K7" 0603R#1 3325,1650 r180 top
R288 "4K7" 0603R#1 3325,1575 r0 top
R289 "1M" 0603R#1 525,1525 r270 top
R290 "0" 0603R#1 1200,1300 r90 top
R291 "10K" 0603R#1 2925,1450 r270 top
R292 "100K" 0603R#1 3300,1450 r90 top
R293 "[N/A]" 0603R#1 1275,1300 r90 top
R294 "100K" 0603R#1 2850,1450 r270 top
R295 "[N/A]" 0603R#1 3000,1450 r270 top
R296 "100" 0603R#1 4150,1250 r0 top
R299 "0" 0603R#1 2950,1149 r180 top
R300 "0" 0603R#1 4150,1150 r180 top
R301 "51" 0603R#1 1426,1124 r0 top
R302 "51" 0603R#1 1426,974 r0 top
R303 "0" 0603R#1 2950,1049 r0 top
R304 "0" 0603R#1 2050,875 r180 top
R305 "680" 0603R#1 2250,875 r90 top
R306 "680" 0603R#1 2325,875 r90 top
R307 "0" 0603R#1 2975,2850 r270 top
R308 "0" 0603R#1 2975,3025 r270 top
R309 "0" 0603R#1 3050,2850 r270 top
R310 "0" 0603R#1 3600,850 r0 top
R311 "0" 0603R#1 3800,750 r180 top
R312 "10K" 0603R#1 2800,875 r270 top
R313 "10K" 0603R#1 2725,875 r270 top
R314 "10K" 0603R#1 2950,849 r180 top
R315 "0" 0603R#1 3450,750 r180 top
R317 "510" 0603R#1 2325,700 r90 top
R318 "0" 0603R#1 2950,749 r0 top
R319 "0" 0603R#1 3450,675 r180 top
R320 "10K" 0603R#1 3800,650 r0 top
R321 "0" 0603R#1 1375,700 r270 top
R322 "100K" 0603R#1 1450,699 r270 top
R323 "2K2" 0603R#1 1525,699 r270 top
R325 "680" 0603R#1 2250,700 r90 top
R326 "100" 0603R#1 2575,700 r90 top
R327 "100" 0603R#1 2800,700 r90 top
R328 "0" 0603R#1 2950,674 r180 top
RS1 "22" RES8B_0402 3325,1800 r270 top
RV1 "3386P-503H[5%]" 3296W 775,300 r180 top
RV2 "10K" 3296W 3625,300 r180 top
SB2 "" JP2_SMD 2800,5775 r270 top
SB5 "" JP2_SMD 1200,5100 r0 top
SB6 "" JP2_SMD 2335,5075 r0 top
SB7 "" JP2_SMD 2250,5075 r180 top
SB8 "" JP2_SMD 2525,5075 r180 top
SB9 "" JP2_SMD 2715,5075 r180 top
SB11 "" JP2_SMD 2950,4650 r180 top
SB12 "" JP2_SMD 2150,3850 r270 top
SB13 "" JP2_SMD 2225,3850 r270 top
SB14 "" JP2_SMD 2300,3850 r270 top
SB15 "" JP2_SMD 2375,3850 r270 top
SB16 "" JP2_SMD 1600,3200 r180 top
SB17 "" JP2_SMD 1600,3125 r180 top
SB18 "" JP2_SMD 1600,3050 r180 top
SB19 "" JP2_SMD 4175,1950 r90 top
SW1 "09.03290.01" SIP3 1175,4150 r0 top
T1 "9013" SOT-23 3900,3800 r0 top
T2 "FDN327N" SOT-23 2675,2275 r90 top
T3 "irlml6302" SOT-23 2850,2275 r90 top
T4 "9013" SOT-23 3500,2075 r90 top
T5 "9013" SOT-23 3650,2075 r90 top
T6 "9013" SOT-23 675,1700 r0 top
T7 "9013" SOT-23 850,1700 r0 top
TP1 "VREF" TP 2975,3625 r0 top
TP2 "VDDA" TP 3050,3175 r0 top
TP3 "VDD" TP 2675,3175 r0 top
TP4 "+3V3" TP 3250,3175 r0 top
TP5 "5V" TP 1025,3125 r0 top
TP6 "+1V8" TP 1425,2950 r0 top
TP7 "VDD_ADJ" TP 1425,2775 r0 top
TP8 "Ground" TP 400,500 r0 top
TP9 "2V5" TP 1100,450 r0 top
TR1 "FDN327N" SOT-23 1825,2400 r0 top
TR2 "FDN327N" SOT-23 1825,2225 r0 top
TR3 "BSN20" SOT-23 3500,2400 r270 top
TS1 "TS_PAD" TS_PAD 2050,5400 r0 top
TS2 "TS_PAD" TS_PAD 2750,5400 r0 top
U1 "STTS751-0WB3F" SOT23-6L 1450,6400 r0 top
U2 "HS1101LF" HS1101LF 4250,4800 r180 top
U3 "SN65HVD230" SO8 3125,4900 r270 top
U4 "STM32F303VCT6" IC149-100-025-B5 2250,4325 r0 top locked
U5 "ST3241EBPR" SSOP28 1325,3525 r0 top
U6 "M24M01-HRMN6T" SO8 3250,3450 r0 top
U7 "USBLC6-2P6 (optional)" SOT-666 3900,4025 r270 top
U8 "SN74LVC2T45DCUT" VSSOP8 575,3525 r270 top
U9 "ST3485EBDR" SO8 1225,3175 r270 top
U10 "TFDU6300" IR_VISHAY3 125,2400 r90 top
U11 "ST1L05BPUR" DFN6(3X3) 1125,2225 r180 top
U12 "CS2200-CP" MSOP10(0.5) 1526,2450 r180 top
U13 "SN74LVC2T45DCUT" VSSOP8 3250,2125 r0 top
U14 "ST1L05BPUR" DFN6(3X3) 1050,1075 r180 top
U15 "STM32F103C8T6" LQFP48 3025,1825 r0 top
U16 "SN74LVC2T45DCUT" VSSOP8 3600,950 r0 top
U17 "LD1117S25TR" SOT-223 1575,1550 r180 top
U18 "TSOP34836" TSOP348 4325,1150 r90 top
U19 "USBLC6-2P6 (optional)" SOT-666 675,1950 r270 top
U20 "SN74LVC2T45DCUT" VSSOP8 3225,1100 r0 top
U21 "BNX002-01" BNX001 225,1275 r180 top
U22 "SN74LVC2T45DCUT" VSSOP8 3225,950 r0 top
U23 "CS42L52" QFN40(6*6) 1775,950 r270 top
U24 "ZEN056V130A24LS" polyzen 525,825 r270 top
U25 "LD1086D2M33" D2PAK/A 1875,1925 r0 top
U26 "KECG2740TBL[N/A]" KEC2740 1300,300 r90 top
U27 "MT008-A" JOY 2450,300 r315 top
U28 "M95M01-RMN6TP" SO8 3200,750 r270 top
X1 "CM200C32.768KDZF" SM8 2000,3400 r180 top
X2 "ESA8.00000F20D25F(with socket)" XTAL_socket 2425,3400 r0 top
X3 "[N/A]" XTAL_socket 1725,2875 r0 top
X4 "8MHz" SMT_XTAL 3150,1275 r180 top
Z1 "SMAJ5.0A-TR" 1R1C 575,1100 r180 top

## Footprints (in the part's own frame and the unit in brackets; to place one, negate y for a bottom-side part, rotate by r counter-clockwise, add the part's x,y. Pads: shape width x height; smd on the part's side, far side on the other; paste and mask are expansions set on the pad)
1R1C [mm]
  rect 2.3x1.75 smd: 1(1.9,0) 2(-1.9,0)
  silkscreen extent -2.2,-1.5 2.2,1.5
2*3P#1 [mil]
  round 60 hole 40: 1(0,0) 2(100,0) 3(0,-100) 4(100,-100) 5(0,-200)
  silkscreen extent -50,-250 150,50
2*3P#2 [mil]
  round 60 hole 40: 1(0,0) 2(100,0) 3(0,-100) 4(100,-100) 5(0,-200) 6(100,-200)
  silkscreen extent -50,-250 150,50
2*4P [mil]
  round 60 hole 40: 1(0,0) 2(100,0) 3(0,-100) 4(100,-100) 5(0,-200) 6(100,-200) 7(0,-300) 8(100,-300)
  silkscreen extent -50,-350 150,50
2*26P [mil]
  round 60 hole 40: 1(0,0) 2(100,0) 3(0,-100) 4(100,-100) 5(0,-200) 6(100,-200) 7(0,-300) 8(100,-300) 9(0,-400) 10(100,-400) 11(0,-500) 12(100,-500) 13(0,-600) 14(100,-600) 15(0,-700) 16(100,-700) 17(0,-800) 18(100,-800) 19(0,-900) 20(100,-900) 21(0,-1000) 22(100,-1000) 23(0,-1100) 24(100,-1100) 25(0,-1200) 26(100,-1200) 27(0,-1300) 28(100,-1300) 29(0,-1400) 30(100,-1400) 31(0,-1500) 32(100,-1500) 33(0,-1600) 34(100,-1600) 35(0,-1700) 36(100,-1700) 37(0,-1800) 38(100,-1800) 39(0,-1900) 40(100,-1900) 41(0,-2000) 42(100,-2000) 43(0,-2100) 44(100,-2100) 45(0,-2200) 46(100,-2200) 47(0,-2300) 48(100,-2300) 49(0,-2400) 50(100,-2400) 51(0,-2500) 52(100,-2500)
  silkscreen extent -50,-2550 150,50
0603C [mil]
  rect 30x30 smd: 1(27.5,0) 2(-27.5,0)
  silkscreen extent -50,-20 50,20
0603D [mil]
  rect 30x30 smd: 1(27.5,0) 2(-27.5,0)
  silkscreen extent -50,-25 55,25
0603L [mil]
  rect 30x30 smd: 1(27.5,0) 2(-27.5,0)
  silkscreen extent -50,-20 50,20
0603R#1 [mil]
  rect 30x30 smd: 1(27.38,0.16) 2(-27.62,0.16)
  silkscreen extent -50,-20 50,20
0603R#2 [mil]
  rect 30x30 smd: 1(27.5,0) 2(-27.5,0)
  silkscreen extent -50,-20 50,20
0805C [mil]
  rect 40x50 smd: 1(40,0) 2(-40,0)
  silkscreen extent -70,-35 70,35
1206C [mil]
  rect 50x60 smd: 1(60,0) 2(-60,0)
  silkscreen extent -95,-40 95,40
2010R [mil]
  rect 70x100 smd: 1(85,0) 2(-85,0)
  silkscreen extent -145,-75 145,75
3296W [mil]
  round 50 hole 28: 1(-100,0) 2(0,100) 3(100,0)
  silkscreen extent -190,-190 190,190
BNX001 [mm]
  round 1.8 hole 1.4: 1(2.5,2.5) 2(-2.5,2.5) 3(2.5,-2.5) 4(0,0) 5(5,0) 6(-2.5,-2.5)
  silkscreen extent -5,-5 5.76,5
C200M [mil]
  rect 100x80 smd paste-23.62 mask-23.62: 1(90,0)
  rect 100x80 smd paste-19.68 mask-19.68: 2(-90,0)
  silkscreen extent -90,-105 95,105
C310M [mil]
  rect 200x120 smd mask-23.62: 1(125,0) 2(-125,0)
  silkscreen extent -163,-163 163,163
D0.1L [mil]
  round 50 hole 30: 1(-50,0) 2(50,0)
  silkscreen extent -84,-361 84,79
D2PAK/A [mm]
  rect 2.8x1 smd: 1(-11.4,2.54) 2(-11.4,0)
  rect 8x10.2 smd: 2(0,0)
  rect 2.8x1.42 smd: 3(-11.4,-2.54)
  silkscreen extent -6.35,-5.08 4.06,5.08
DB9/M [mil]
  round 50 hole 50: 0(-538,55) 0(-523,55) 0(-508,55) 0(-493,55) 0(-478,55) 0(-463,55) 0(-448,55) 0(448,55) 0(463,55) 0(478,55) 0(493,55) 0(508,55) 0(523,55) 0(538,55)
  oval 170x80 hole 50: 0(-493,55) 0(493,55)
  rect 70x80 hole 38: 1(218,0)
  oval 70x80 hole 38: 2(109,0) 3(0,0) 4(-109,0) 5(-218,0) 6(164,110) 7(55,110) 8(-54,110) 9(-163,110)
  silkscreen extent -618,-100 618,410
DC10B [mil]
  round 45 hole 30: 1(244.09,-40) 1(244.09,-20) 1(244.09,20) 1(244.09,40) 2(82.05,-196.85) 2(102.05,-196.85) 2(142.05,-196.85) 2(162.05,-196.85) 3(0,-40) 3(0,-20) 3(0,20) 3(0,40)
  oval 80x180 hole 30: 1(244.1,0) 3(0,0)
  oval 180x80 hole 30: 2(122.05,-196.85)
  silkscreen extent -175,-170 290,180
DFN6(3X3) [mm]
  rect 2x1.2 smd: 0(0,0)
  rect 0.45x0.5 smd: 1(-0.95,-1.3) 2(0,-1.3) 3(0.95,-1.3) 4(0.95,1.3) 5(0,1.3) 6(-0.95,1.3)
  silkscreen extent -1.5,-1.3 1.5,1.3
FTSH-110-01-L-DV [mil]
  round 25 hole 38 unplated: 0(-200,0) 0(200,0)
  rect 25x100 smd: 1(-225,-85) 2(-225,85) 3(-175,-85) 4(-175,85) 5(-125,-85) 6(-125,85) 7(-75,-85) 8(-75,85) 9(-25,-85) 10(-25,85) 11(25,-85) 12(25,85) 13(75,-85) 14(75,85) 15(125,-85) 16(125,85) 17(175,-85) 18(175,85) 19(225,-85) 20(225,85)
  silkscreen extent -275,-102 275,102
HS1101LF [mil]
  round 50 hole 30: 1(100,0) 2(-100,0)
  silkscreen extent -177,-177 177,177
IC149-100-025-B5 [mm]
  rect 1x2.5 smd rot 45: 0(-8.1,-8.1) 0(8.1,8.1)
  rect 1x2.5 smd rot 135: 0(-8.1,8.1) 0(8.1,-8.1)
  round 1.5 hole 1.5 unplated: 0(-5,0) 0(5,0)
  rect 0.25x1.65 smd: 1(-6,-7.725) 2(-5.5,-7.725) 3(-5,-7.725) 4(-4.5,-7.725) 5(-4,-7.725) 6(-3.5,-7.725) 7(-3,-7.725) 8(-2.5,-7.725) 9(-2,-7.725) 10(-1.5,-7.725) 11(-1,-7.725) 12(-0.5,-7.725) 13(0,-7.725) 14(0.5,-7.725) 15(1,-7.725) 16(1.5,-7.725) 17(2,-7.725) 18(2.5,-7.725) 19(3,-7.725) 20(3.5,-7.725) 21(4,-7.725) 22(4.5,-7.725) 23(5,-7.725) 24(5.5,-7.725) 25(6,-7.725) 51(6,7.725) 52(5.5,7.725) 53(5,7.725) 54(4.5,7.725) 55(4,7.725) 56(3.5,7.725) 57(3,7.725) 58(2.5,7.725) 59(2,7.725) 60(1.5,7.725) 61(1,7.725) 62(0.5,7.725) 63(0,7.725) 64(-0.5,7.725) 65(-1,7.725) 66(-1.5,7.725) 67(-2,7.725) 68(-2.5,7.725) 69(-3,7.725) 70(-3.5,7.725) 71(-4,7.725) 72(-4.5,7.725) 73(-5,7.725) 74(-5.5,7.725) 75(-6,7.725)
  rect 1.65x0.25 smd: 26(7.725,-6) 27(7.725,-5.5) 28(7.725,-5) 29(7.725,-4.5) 30(7.725,-4) 31(7.725,-3.5) 32(7.725,-3) 33(7.725,-2.5) 34(7.725,-2) 35(7.725,-1.5) 36(7.725,-1) 37(7.725,-0.5) 38(7.725,0) 39(7.725,0.5) 40(7.725,1) 41(7.725,1.5) 42(7.725,2) 43(7.725,2.5) 44(7.725,3) 45(7.725,3.5) 46(7.725,4) 47(7.725,4.5) 48(7.725,5) 49(7.725,5.5) 50(7.725,6) 76(-7.725,6) 77(-7.725,5.5) 78(-7.725,5) 79(-7.725,4.5) 80(-7.725,4) 81(-7.725,3.5) 82(-7.725,3) 83(-7.725,2.5) 84(-7.725,2) 85(-7.725,1.5) 86(-7.725,1) 87(-7.725,0.5) 88(-7.725,0) 89(-7.725,-0.5) 90(-7.725,-1) 91(-7.725,-1.5) 92(-7.725,-2) 93(-7.725,-2.5) 94(-7.725,-3) 95(-7.725,-3.5) 96(-7.725,-4) 97(-7.725,-4.5) 98(-7.725,-5) 99(-7.725,-5.5) 100(-7.725,-6)
  silkscreen extent -6.73,-6.73 6.73,6.73
IDC20S [mil]
  round 60 hole 40: 1(0,0) 2(100,0) 3(0,-100) 4(100,-100) 5(0,-200) 6(100,-200) 7(0,-300) 8(100,-300) 9(0,-400) 10(100,-400) 11(0,-500) 12(100,-500) 13(0,-600) 14(100,-600) 15(0,-700) 16(100,-700) 17(0,-800) 18(100,-800) 19(0,-900) 20(100,-900)
  silkscreen extent -125,-1100 250,200
IDC34S [mil]
  round 60 hole 40: 1(0,0) 2(100,0) 3(0,-100) 4(100,-100) 5(0,-200) 6(100,-200) 7(0,-300) 8(100,-300) 9(0,-400) 10(100,-400) 11(0,-500) 12(100,-500) 13(0,-600) 14(100,-600) 15(0,-700) 16(100,-700) 17(0,-800) 18(100,-800) 19(0,-900) 20(100,-900) 21(0,-1000) 22(100,-1000) 23(0,-1100) 24(100,-1100) 25(0,-1200) 26(100,-1200) 27(0,-1300) 28(100,-1300) 29(0,-1400) 30(100,-1400) 31(0,-1500) 32(100,-1500) 33(0,-1600) 34(100,-1600)
  silkscreen extent -125,-1800 250,200
IR_VISHAY3 [mm]
  rect 0.5x2 smd: 1(3.325,0) 2(2.375,0) 3(1.425,0) 4(0.475,0) 5(-0.475,0) 6(-1.425,0) 7(-2.375,0) 8(-3.325,0)
  silkscreen extent -4.18,-1.1 4.33,4.17
JOY [mil]
  rect 40x70 smd: 0(-140,0) 0(145,0) 1(-55.12,-122.05) 2(0,-122.05) 3(55.12,-122.05) 4(55.12,122.05) 5(0,122.05) 6(-55.12,122.05)
  round 27.56 hole 27.56 unplated: G(-74.8,0)
  round 39.37 hole 39.37 unplated: G(74.8,0)
  silkscreen extent -141,-150 146,150
JP2_SMD [mil]
  oct 15x30 smd rot 45: 1(-18,-8) 2(18,7)
  oct 15.75x30 smd rot 135: 1(-18,8)
  rect 26x26 smd rot 45: 2(13,0)
  oct 15x30 smd rot 135: 2(18,-7)
KEC2740 [mm]
  round 1.27 hole 0.762: 1(-1,-0.95) 2(-1,0.95)
  silkscreen extent -3,-3 3,3
LED2-28*32 [mm]
  rect 1.1x1.5 smd: 1(-0.75,-1.5) 2(-0.75,1.5) 3(0.75,1.5) 4(0.75,-1.5)
  silkscreen extent -1.27,-0.64 1.27,0.64
LI1220_1 [mm]
  round 1.1 hole 1.1 unplated: 0(-3.75,0)
  round 1.5 hole 1.5 unplated: 0(3.75,0.025)
  oct 4x2.5 smd: 1(8.255,0) 2(-8.128,0)
  silkscreen extent -7.57,-7.62 7.57,7.62
LQFP48 [mm]
  rect 0.2x1 smd: 1(-2.75,-4.25) 2(-2.25,-4.25) 3(-1.75,-4.25) 4(-1.25,-4.25) 5(-0.75,-4.25) 6(-0.25,-4.25) 7(0.25,-4.25) 8(0.75,-4.25) 9(1.25,-4.25) 10(1.75,-4.25) 11(2.25,-4.25) 12(2.75,-4.25) 25(2.75,4.25) 26(2.25,4.25) 27(1.75,4.25) 28(1.25,4.25) 29(0.75,4.25) 30(0.25,4.25) 31(-0.25,4.25) 32(-0.75,4.25) 33(-1.25,4.25) 34(-1.75,4.25) 35(-2.25,4.25) 36(-2.75,4.25)
  rect 1x0.2 smd: 13(4.25,-2.75) 14(4.25,-2.25) 15(4.25,-1.75) 16(4.25,-1.25) 17(4.25,-0.75) 18(4.25,-0.25) 19(4.25,0.25) 20(4.25,0.75) 21(4.25,1.25) 22(4.25,1.75) 23(4.25,2.25) 24(4.25,2.75) 37(-4.25,2.75) 38(-4.25,2.25) 39(-4.25,1.75) 40(-4.25,1.25) 41(-4.25,0.75) 42(-4.25,0.25) 43(-4.25,-0.25) 44(-4.25,-0.75) 45(-4.25,-1.25) 46(-4.25,-1.75) 47(-4.25,-2.25) 48(-4.25,-2.75)
  silkscreen extent -3.81,-3.81 3.81,3.81
markpoint_1.0 [mil]
  round 40 smd: 0(0,0)
MB895CS [mil]
  round 125.98 hole 125.98 unplated: 0(-3048.94,-1462.72) 0(-3048.94,-45)
  round 60 hole 40: 1(0,0) 2(100,0) 3(0,-100) 4(100,-100) 5(0,-200) 6(100,-200) 7(0,-300) 8(100,-300) 9(0,-1000) 10(100,-1000) 11(0,-1100) 12(100,-1100) 13(0,-1200) 14(100,-1200) 15(0,-1300) 16(100,-1300)
  silkscreen extent -3148,-1620 174,110
MS22D16 [mil]
  round 60 hole 40: 1(-98.43,-66.93) 2(0,-66.93) 3(98.43,-66.93) 4(-98.43,66.93) 5(0,66.93) 6(98.43,66.93)
  silkscreen extent -177,-67 177,149
MSD(PJS008) [mm]
  rect 1.4x3.5 smd: 0(-3.503,-7.357)
  rect 1.6x3.5 smd: 0(-3.4,3.65)
  rect 1.5x3.1 smd: 0(11.45,-7.35)
  rect 1.2x3.1 smd: 0(11.6,4.15)
  rect 0.8x1.6 smd: 1(1.475,5.8) 2(2.575,5.8) 3(3.675,5.8) 4(4.775,5.8) 5(5.875,5.8) 6(6.975,5.8) 7(8.075,5.8) 8(9.175,5.8)
  rect 0.85x1.6 smd: 9(10.325,5.8)
  rect 1.95x1.4 smd: 10(11.225,-4.4)
  round 0.7 hole 0.7 unplated: g(0,0) g(7.55,0)
  silkscreen extent -3.81,-9.28 11.43,5.07
MSOP10(0.5) [mm]
  rect 0.3x0.9 smd: 1(-1,-2.151) 2(-0.5,-2.151) 3(0,-2.151) 4(0.5,-2.151) 5(1,-2.151) 6(1,2.151) 7(0.5,2.151) 8(0,2.151) 9(-0.5,2.151) 10(-1,2.151)
  silkscreen extent -1.35,-1.36 1.32,1.36
PB10 [mm]
  rect 1.5x1 smd paste+0.381 mask+0: 1(-4.5,-2.222) 2(-4.5,2.222) 3(4.5,2.222) 4(4.5,-2.222)
  silkscreen extent -3.17,-3.17 3.17,3.17
PJ3028B [mm]
  rect 1.2x2.5 smd: 2(-3.9,-4) 7(-2,4)
  rect 2x2.5 smd: 3(-1,-4) 4(0.8,4) 6(8.2,-4)
  rect 2.5x2 smd: 5(12.25,0.8)
  round 2 hole 2 unplated: G1(0,0) G2(7,0)
  silkscreen extent -5.71,-3.05 10.92,3.05
PLCC4 [mm]
  rect 0.9x1.3 smd: 1(-0.75,-1.65) 2(0.75,-1.65) 3(-1,-0.05) 4(1,-0.05) 5(-0.75,1.65) 6(0.75,1.65)
  silkscreen extent -1.4,-1.6 1.4,1.6
polyzen [mm]
  rect 0.8x2.21 smd: 1(1.714,0)
  rect 0.7x0.94 smd: 2(-1.714,-0.635) 3(-1.714,0.635)
  silkscreen extent -1.97,-2.03 2.1,2.03
PVT901 [mil]
  round 60 hole 30: 1(0,50) 2(0,-50)
  silkscreen extent -92,-98 92,98
QFN40(6*6) [mm]
  rect 4x4 smd: 0(0,0)
  rect 0.6x0.2 smd: 1(-2.87,2.25) 2(-2.87,1.75) 3(-2.87,1.25) 4(-2.87,0.75) 5(-2.87,0.25) 6(-2.87,-0.25) 7(-2.87,-0.75) 8(-2.87,-1.25) 9(-2.87,-1.75) 10(-2.87,-2.25) 21(2.87,-2.25) 22(2.87,-1.75) 23(2.87,-1.25) 24(2.87,-0.75) 25(2.87,-0.25) 26(2.87,0.25) 27(2.87,0.75) 28(2.87,1.25) 29(2.87,1.75) 30(2.87,2.25)
  rect 0.2x0.6 smd: 11(-2.25,-2.87) 12(-1.75,-2.87) 13(-1.25,-2.87) 14(-0.75,-2.87) 15(-0.25,-2.87) 16(0.25,-2.87) 17(0.75,-2.87) 18(1.25,-2.87) 19(1.75,-2.87) 20(2.25,-2.87) 31(2.25,2.87) 32(1.75,2.87) 33(1.25,2.87) 34(0.75,2.87) 35(0.25,2.87) 36(-0.25,2.87) 37(-0.75,2.87) 38(-1.25,2.87) 39(-1.75,2.87) 40(-2.25,2.87)
  silkscreen extent -3,-3 3,3
RES8B_0402 [mil]
  rect 10x15 smd: 1(-68.9,-31) 2(-68.9,31) 3(-49.21,-31) 4(-49.21,31) 5(-29.53,-31) 6(-29.53,31) 7(-9.84,-31) 8(-9.84,31) 9(9.84,-31) 10(9.84,31) 11(29.53,-31) 12(29.53,31) 13(49.21,-31) 14(49.21,31) 15(68.9,-31) 16(68.9,31)
  silkscreen extent -83,-20 83,20
SIP2 [mil]
  round 60 hole 40: 1(0,0) 2(100,0)
  silkscreen extent -50,-50 150,50
SIP3 [mil]
  rect 60x60 hole 40: 1(0,0)
  round 60 hole 40: 2(100,0) 3(200,0)
  silkscreen extent -50,-50 250,50
SLF10145 [mm]
  rect 2.5x3.2 smd: 1(4.05,0) 2(-4.05,0)
  silkscreen extent -5.08,-5.08 5.08,5.08
SM8 [mm]
  rect 1.9x1.3 smd: 1(-2.75,-1.6) 2(2.75,-1.6) 3(2.75,1.6) 4(-2.75,1.6)
  silkscreen extent -4.44,-1.91 4.44,1.91
SMB [mm]
  rect 1.52x2.3 smd: 1(2.135,0) 2(-2.135,0)
  silkscreen extent -1.88,-2.02 1.88,2.02
SMT_XTAL [mil]
  rect 150x50 smd mask-11.81: 1(-195,0) 2(195,0)
  silkscreen extent -214,-89 214,89
SO8 [mil]
  rect 20x60 smd: 1(-75,-112.5) 2(-25,-112.5) 3(25,-112.5) 4(75,-112.5) 5(75,112.5) 6(25,112.5) 7(-25,112.5) 8(-75,112.5)
  silkscreen extent -105,-53 105,48
SOD-123 [mil]
  rect 38.19x30 smd: 1(60,0) 2(-60,0)
  silkscreen extent -55,-31 55,31
SOD-323 [mm]
  rect 0.6x0.45 smd: 1(1.143,0) 2(-1.143,0)
  silkscreen extent -0.67,-0.57 0.67,0.57
SOT23-6L [mm]
  rect 0.4x0.9 smd: 1(-0.95,-1.05) 2(0,-1.05) 3(0.95,-1.05) 4(0.95,1.05) 5(0,1.05) 6(-0.95,1.05)
  silkscreen extent -1.45,-0.55 1.25,0.55
SOT-23 [mil]
  rect 36x36 smd: 1(40,37.5) 2(40,-37.5)
  rect 50x36 smd: 3(-40,0.5)
  silkscreen extent -45,-58 45,58
SOT-223 [mil]
  rect 80x40 smd: 1(110,-90.55) 2(110,0) 3(110,90.55)
  rect 90x120 smd: 2(-110,0)
  silkscreen extent -50,-126 50,134
SOT-666 [mil]
  rect 11x40 smd: 1(-19.68,-31.3) 2(0,-31.3) 3(19.68,-31.3) 4(19.68,31.3) 5(0,31.3) 6(-19.68,31.3)
  silkscreen extent -35,-32 35,32
SS42D02 [mm]
  round 2.032 hole 1.397: 0(-6.5,3.25) 0(-6.5,-3.25) 0(6.5,-3.25) 0(6.5,3.25)
  round 1.27 hole 0.762: 1(-5,-1.25) 2(-3,-1.25) 3(-1,-1.25) 4(1,-1.25) 5(3,-1.25) 6(5,-1.25) 7(1,1.25) 8(3,1.25) 9(5,1.25) 10(-5,1.25) 11(-3,1.25) 12(-1,1.25)
  silkscreen extent -7.3,-3.4 7.3,3.5
SSM-104-L-DH [mm]
  round 1.2 hole 1.2 unplated: 0(0,-2.54) 0(0,2.54)
  rect 2x1 smd: 1(5.143,3.81) 3(5.143,1.27) 5(5.143,-1.27) 7(5.143,-3.81)
  rect 1.905x1.016 smd: 2(-5.143,3.81)
  rect 2x1.1 smd: 4(-5.143,1.27) 6(-5.143,-1.27) 8(-5.143,-3.81)
  silkscreen extent -3.81,-5.08 3.87,5.08
SSOP28 [mm]
  rect 0.95x0.3 smd: 1(-3.8,4.225) 2(-3.8,3.575) 3(-3.8,2.925) 4(-3.8,2.275) 5(-3.8,1.625) 6(-3.8,0.975) 7(-3.8,0.325) 8(-3.8,-0.325) 9(-3.8,-0.975) 10(-3.8,-1.625) 11(-3.8,-2.275) 12(-3.8,-2.925) 13(-3.8,-3.575) 14(-3.8,-4.225) 15(3.8,-4.225) 16(3.8,-3.575) 17(3.8,-2.925) 18(3.8,-2.275) 19(3.8,-1.625) 20(3.8,-0.975) 21(3.8,-0.325) 22(3.8,0.325) 23(3.8,0.975) 24(3.8,1.625) 25(3.8,2.275) 26(3.8,2.925) 27(3.8,3.575) 28(3.8,4.225)
  silkscreen extent -2.56,-4.55 2.56,4.55
TAN-A [mil]
  rect 50x60 smd: 1(55,0) 2(-55,0)
  silkscreen extent -95,-45 105,45
TP [mil]
  round 60 hole 40: 1(0,0)
  silkscreen extent -45,-45 45,45
TS_PAD [mm]
  round 10 smd: 1(0,0)
TSOP348 [mil]
  rect 50x50 hole 30: 1(0,0)
  round 50 hole 30: 2(100,-1) 3(200,1)
  silkscreen extent -47,-155 248,72
USB-B [mil]
  round 120 hole 95: 0(-291,-185) 0(189,-185)
  round 50 hole 30: 1(0,0) 2(-98,0) 3(-98,-80) 4(0,-80)
  silkscreen extent -365,-591 263,57
VSSOP8 [mm]
  rect 0.5x0.25 smd: 1(-1.5,0.75) 2(-1.5,0.25) 3(-1.5,-0.25) 4(-1.5,-0.75) 5(1.5,-0.75) 6(1.5,-0.25) 7(1.5,0.25) 8(1.5,0.75)
  silkscreen extent -1.09,-1 1.09,1
XTAL_socket [mil]
  round 80 hole 53: 1(100,0) 2(-100,0)
  silkscreen extent -215,-89 214,89

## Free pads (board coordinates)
  round 137.8 hole 137.8 unplated: 0(200,225) 0(200,6575) 0(4250,225) 0(4250,6575)
  round 137.79 hole 137.79 unplated: 0(1691.34,5400) 0(3108.66,5400)

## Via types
v1: diameter 16, hole 8, TopLayer to BottomLayer, tented both sides, 770 vias
v2: diameter 16, hole 8, TopLayer to BottomLayer, 26 vias
v3: diameter 25, hole 16, TopLayer to BottomLayer, tented both sides, 17 vias
v4: diameter 50, hole 28, TopLayer to BottomLayer, tented both sides, 4 vias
